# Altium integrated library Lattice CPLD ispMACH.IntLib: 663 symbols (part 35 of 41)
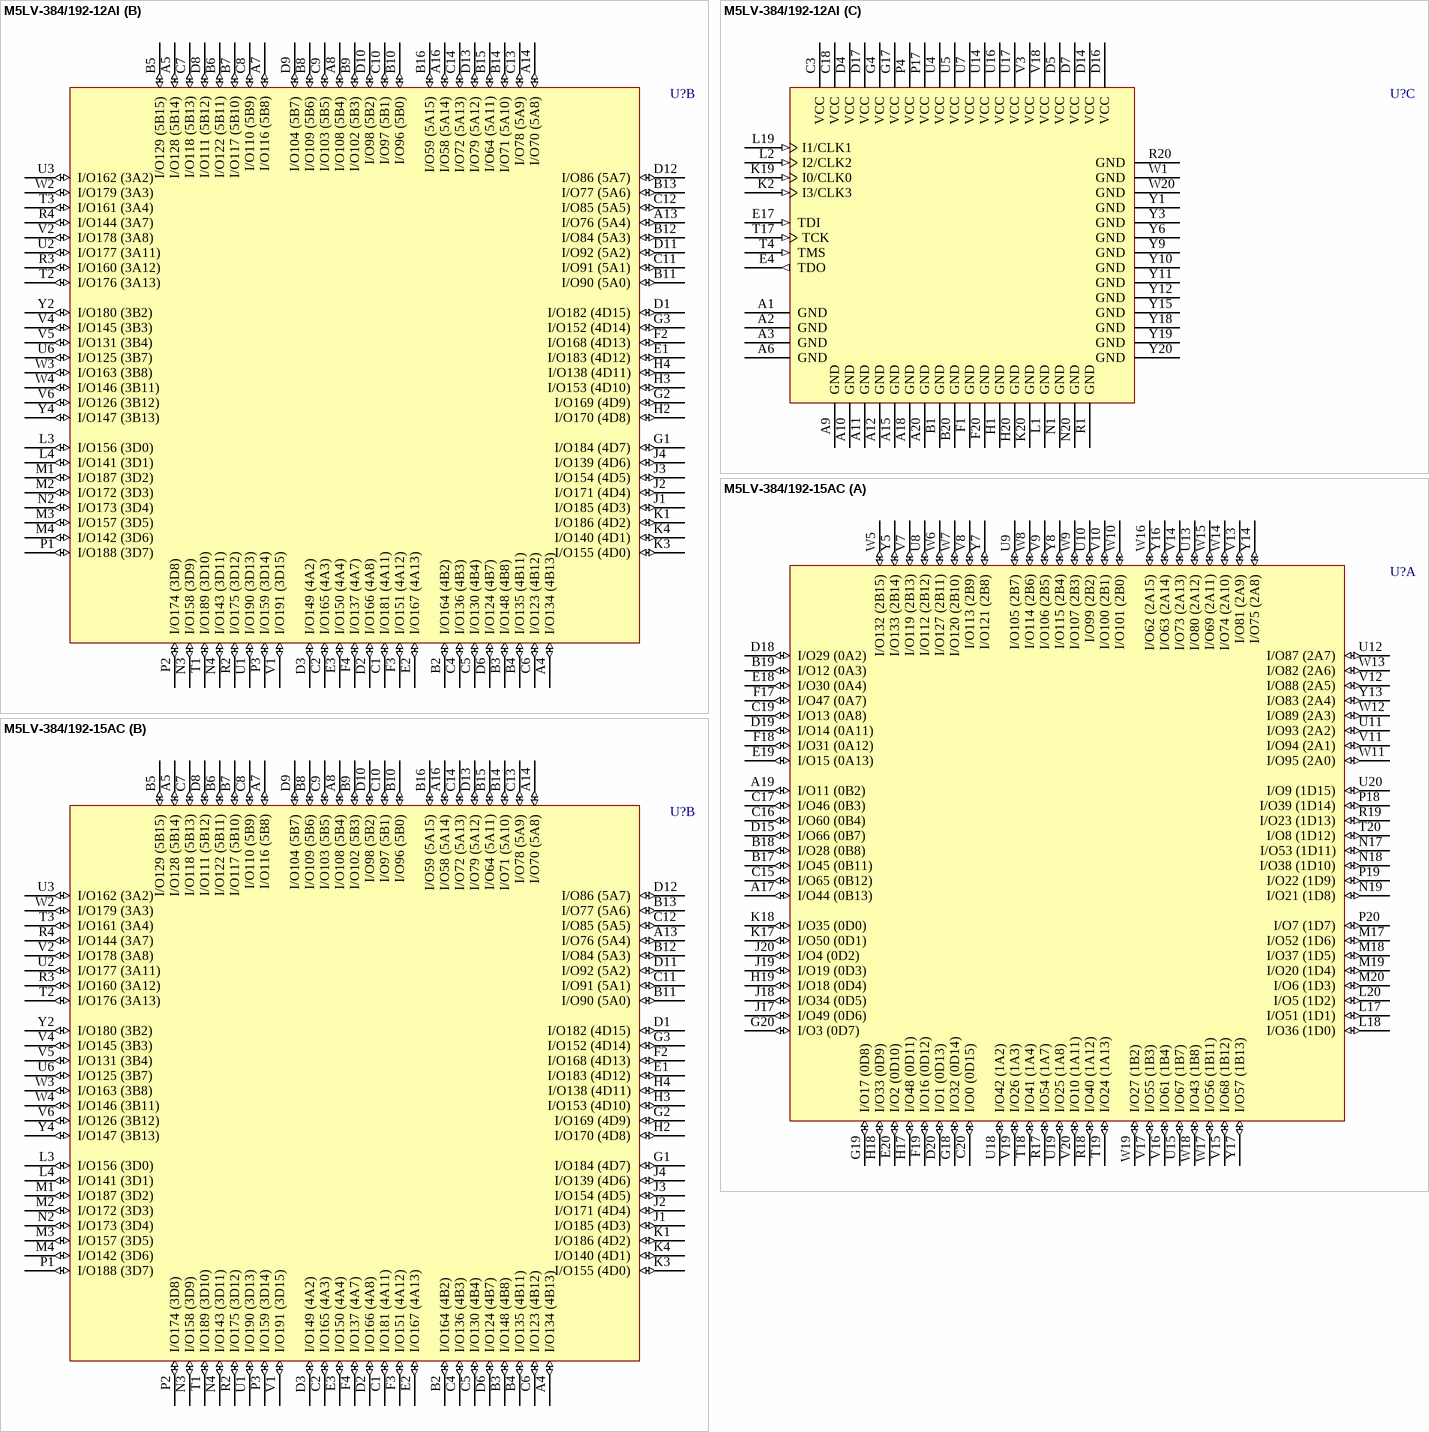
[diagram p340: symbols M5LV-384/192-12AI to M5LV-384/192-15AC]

## M5LV-384/192-12AI
designator U?
High-Density and High-I/O Complex PLD
footprint SBGA256 (BGA, 256-Leads, Body 27x27mm, Pitch 1.27mm)
3D model M5LV-SBGA256 (256-Ball Super Ball Grid Array (SBGA256))
part A pins: A17 I/O44 (0B13) (io), A19 I/O11 (0B2) (io), B17 I/O45 (0B11) (io), B18 I/O28 (0B8) (io), B19 I/O12 (0A3) (io), C15 I/O65 (0B12) (io), C16 I/O60 (0B4) (io), C17 I/O46 (0B3) (io), C19 I/O13 (0A8) (io), C20 I/O0 (0D15) (io), D15 I/O66 (0B7) (io), D18 I/O29 (0A2) (io), D19 I/O14 (0A11) (io), D20 I/O1 (0D13) (io), E18 I/O30 (0A4) (io), E19 I/O15 (0A13) (io), E20 I/O2 (0D10) (io), F17 I/O47 (0A7) (io), F18 I/O31 (0A12) (io), F19 I/O16 (0D12) (io), G18 I/O32 (0D14) (io), G19 I/O17 (0D8) (io), G20 I/O3 (0D7) (io), H17 I/O48 (0D11) (io), H18 I/O33 (0D9) (io), H19 I/O18 (0D4) (io), J17 I/O49 (0D6) (io), J18 I/O34 (0D5) (io), J19 I/O19 (0D3) (io), J20 I/O4 (0D2) (io), K17 I/O50 (0D1) (io), K18 I/O35 (0D0) (io), L17 I/O51 (1D1) (io), L18 I/O36 (1D0) (io), L20 I/O5 (1D2) (io), M17 I/O52 (1D6) (io), M18 I/O37 (1D5) (io), M19 I/O20 (1D4) (io), M20 I/O6 (1D3) (io), N17 I/O53 (1D11) (io), N18 I/O38 (1D10) (io), N19 I/O21 (1D8) (io), P18 I/O39 (1D14) (io), P19 I/O22 (1D9) (io), P20 I/O7 (1D7) (io), R17 I/O54 (1A7) (io), R18 I/O40 (1A12) (io), R19 I/O23 (1D13) (io), T18 I/O41 (1A4) (io), T19 I/O24 (1A13) (io), T20 I/O8 (1D12) (io), U8 I/O112 (2B12) (io), U9 I/O105 (2B7) (io), U10 I/O99 (2B2) (io), U11 I/O93 (2A2) (io), U12 I/O87 (2A7) (io), U13 I/O80 (2A12) (io), U15 I/O67 (1B7) (io), U18 I/O42 (1A2) (io), U19 I/O25 (1A8) (io), U20 I/O9 (1D15) (io), V7 I/O119 (2B13) (io), V8 I/O113 (2B9) (io), V9 I/O106 (2B5) (io), V10 I/O100 (2B1) (io), V11 I/O94 (2A1) (io), V12 I/O88 (2A5) (io), V13 I/O81 (2A9) (io), V14 I/O73 (2A13) (io), V15 I/O68 (1B12) (io), V16 I/O61 (1B4) (io), V17 I/O55 (1B3) (io), V19 I/O26 (1A3) (io), V20 I/O10 (1A11) (io), W5 I/O132 (2B15) (io), W6 I/O127 (2B11) (io), W7 I/O120 (2B10) (io), W8 I/O114 (2B6) (io), W9 I/O107 (2B3) (io), W10 I/O101 (2B0) (io), W11 I/O95 (2A0) (io), W12 I/O89 (2A3) (io), W13 I/O82 (2A6) (io), W14 I/O74 (2A10) (io), W15 I/O69 (2A11) (io), W16 I/O62 (2A15) (io), W17 I/O56 (1B11) (io), W18 I/O43 (1B8) (io), W19 I/O27 (1B2) (io), Y5 I/O133 (2B14) (io), Y7 I/O121 (2B8) (io), Y8 I/O115 (2B4) (io), Y13 I/O83 (2A4) (io), Y14 I/O75 (2A8) (io), Y16 I/O63 (2A14) (io), Y17 I/O57 (1B13) (io)
part B pins: A4 I/O134 (4B13) (io), A5 I/O128 (5B14) (io), A7 I/O116 (5B8) (io), A8 I/O108 (5B4) (io), A13 I/O76 (5A4) (io), A14 I/O70 (5A8) (io), A16 I/O58 (5A14) (io), B2 I/O164 (4B2) (io), B3 I/O148 (4B8) (io), B4 I/O135 (4B11) (io), B5 I/O129 (5B15) (io), B6 I/O122 (5B11) (io), B7 I/O117 (5B10) (io), B8 I/O109 (5B6) (io), B9 I/O102 (5B3) (io), B10 I/O96 (5B0) (io), B11 I/O90 (5A0) (io), B12 I/O84 (5A3) (io), B13 I/O77 (5A6) (io), B14 I/O71 (5A10) (io), B15 I/O64 (5A11) (io), B16 I/O59 (5A15) (io), C1 I/O181 (4A11) (io), C2 I/O165 (4A3) (io), C4 I/O136 (4B3) (io), C5 I/O130 (4B4) (io), C6 I/O123 (4B12) (io), C7 I/O118 (5B13) (io), C8 I/O110 (5B9) (io), C9 I/O103 (5B5) (io), C10 I/O97 (5B1) (io), C11 I/O91 (5A1) (io), C12 I/O85 (5A5) (io), C13 I/O78 (5A9) (io), C14 I/O72 (5A13) (io), D1 I/O182 (4D15) (io), D2 I/O166 (4A8) (io), D3 I/O149 (4A2) (io), D6 I/O124 (4B7) (io), D8 I/O111 (5B12) (io), D9 I/O104 (5B7) (io), D10 I/O98 (5B2) (io), D11 I/O92 (5A2) (io), D12 I/O86 (5A7) (io), D13 I/O79 (5A12) (io), E1 I/O183 (4D12) (io), E2 I/O167 (4A13) (io), E3 I/O150 (4A4) (io), F2 I/O168 (4D13) (io), F3 I/O151 (4A12) (io), F4 I/O137 (4A7) (io), G1 I/O184 (4D7) (io), G2 I/O169 (4D9) (io), G3 I/O152 (4D14) (io), H2 I/O170 (4D8) (io), H3 I/O153 (4D10) (io), H4 I/O138 (4D11) (io), J1 I/O185 (4D3) (io), J2 I/O171 (4D4) (io), J3 I/O154 (4D5) (io), J4 I/O139 (4D6) (io), K1 I/O186 (4D2) (io), K3 I/O155 (4D0) (io), K4 I/O140 (4D1) (io), L3 I/O156 (3D0) (io), L4 I/O141 (3D1) (io), M1 I/O187 (3D2) (io), M2 I/O172 (3D3) (io), M3 I/O157 (3D5) (io), M4 I/O142 (3D6) (io), N2 I/O173 (3D4) (io), N3 I/O158 (3D9) (io), N4 I/O143 (3D11) (io), P1 I/O188 (3D7) (io), P2 I/O174 (3D8) (io), P3 I/O159 (3D14) (io), R2 I/O175 (3D12) (io), R3 I/O160 (3A12) (io), R4 I/O144 (3A7) (io), T1 I/O189 (3D10) (io), T2 I/O176 (3A13) (io), T3 I/O161 (3A4) (io), U1 I/O190 (3D13) (io), U2 I/O177 (3A11) (io), U3 I/O162 (3A2) (io), U6 I/O125 (3B7) (io), V1 I/O191 (3D15) (io), V2 I/O178 (3A8) (io), V4 I/O145 (3B3) (io), V5 I/O131 (3B4) (io), V6 I/O126 (3B12) (io), W2 I/O179 (3A3) (io), W3 I/O163 (3B8) (io), W4 I/O146 (3B11) (io), Y2 I/O180 (3B2) (io), Y4 I/O147 (3B13) (io)
part C pins: A1 GND (power), A2 GND (power), A3 GND (power), A6 GND (power), A9 GND (power), A10 GND (power), A11 GND (power), A12 GND (power), A15 GND (power), A18 GND (power), A20 GND (power), B1 GND (power), B20 GND (power), C3 VCC (power), C18 VCC (power), D4 VCC (power), D5 VCC (power), D7 VCC (power), D14 VCC (power), D16 VCC (power), D17 VCC (power), E4 TDO (out), E17 TDI (in), F1 GND (power), F20 GND (power), G4 VCC (power), G17 VCC (power), H1 GND (power), H20 GND (power), K2 I3/CLK3 (in), K19 I0/CLK0 (in), K20 GND (power), L1 GND (power), L2 I2/CLK2 (in), L19 I1/CLK1 (in), N1 GND (power), N20 GND (power), P4 VCC (power), P17 VCC (power), R1 GND (power), R20 GND (power), T4 TMS (in), T17 TCK (in), U4 VCC (power), U5 VCC (power), U7 VCC (power), U14 VCC (power), U16 VCC (power), U17 VCC (power), V3 VCC (power), V18 VCC (power), W1 GND (power), W20 GND (power), Y1 GND (power), Y3 GND (power), Y6 GND (power), Y9 GND (power), Y10 GND (power), Y11 GND (power), Y12 GND (power), Y15 GND (power), Y18 GND (power), Y19 GND (power), Y20 GND (power)

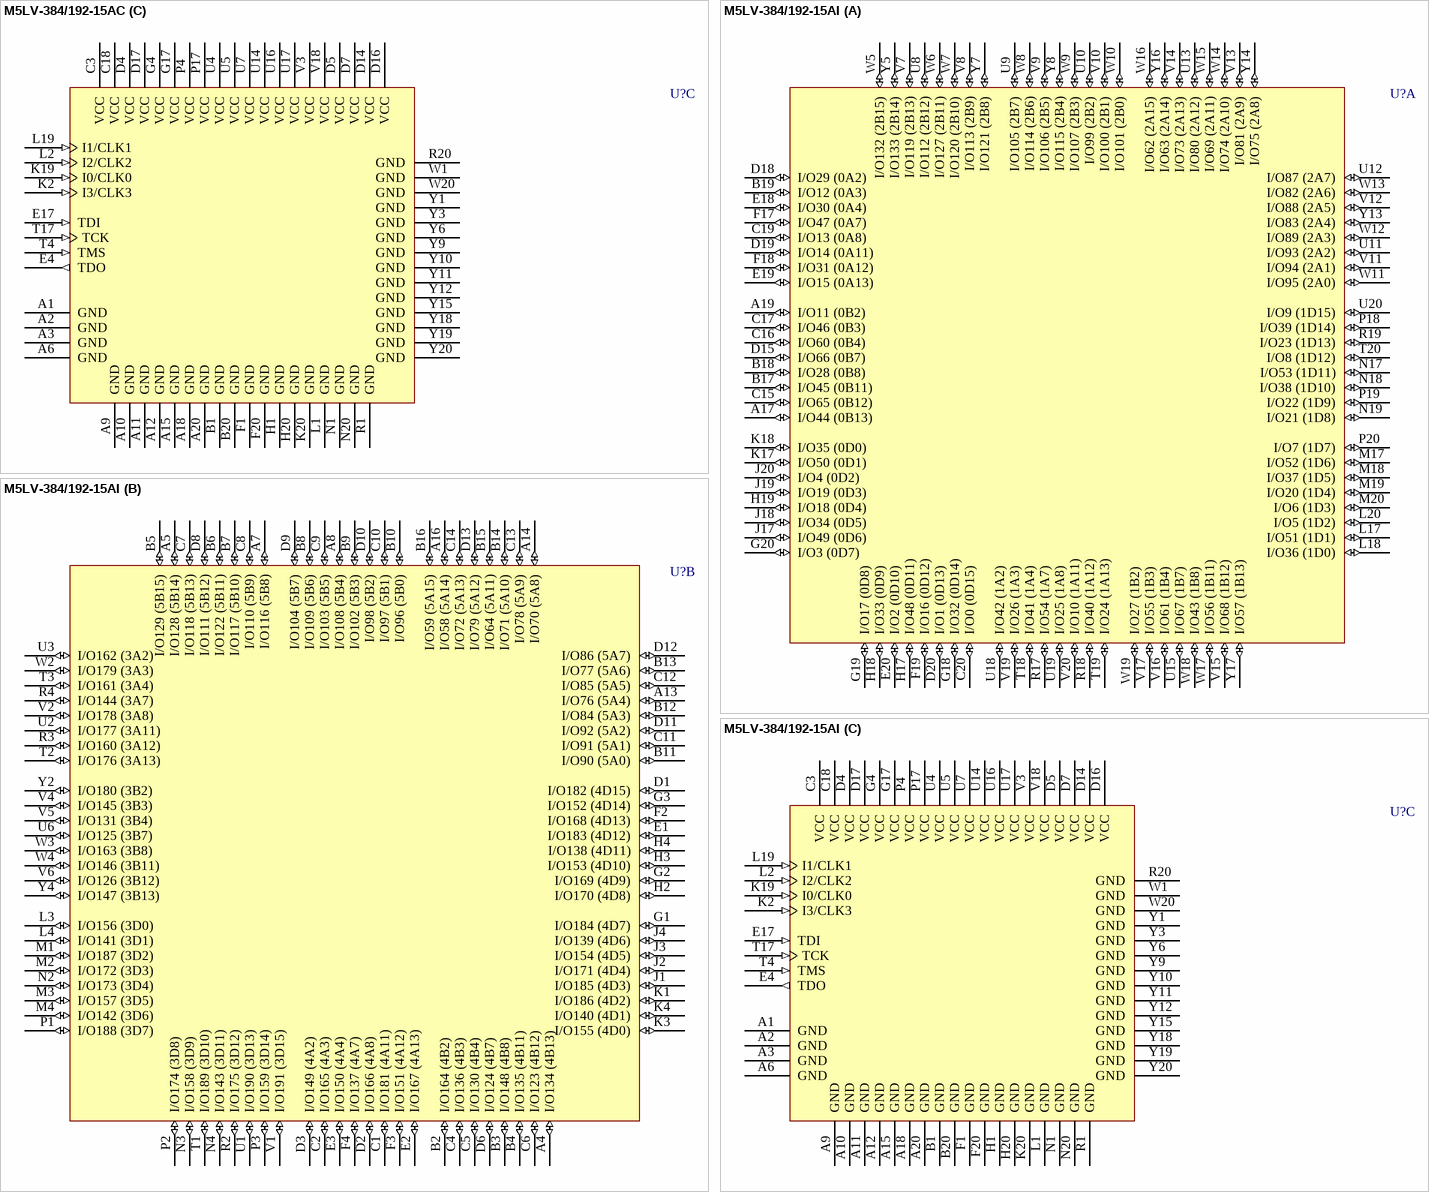
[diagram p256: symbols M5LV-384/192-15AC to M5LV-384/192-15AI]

## M5LV-384/192-15AC
designator U?
High-Density and High-I/O Complex PLD
footprint SBGA256 (BGA, 256-Leads, Body 27x27mm, Pitch 1.27mm)
3D model M5LV-SBGA256 (256-Ball Super Ball Grid Array (SBGA256))
part A pins: A17 I/O44 (0B13) (io), A19 I/O11 (0B2) (io), B17 I/O45 (0B11) (io), B18 I/O28 (0B8) (io), B19 I/O12 (0A3) (io), C15 I/O65 (0B12) (io), C16 I/O60 (0B4) (io), C17 I/O46 (0B3) (io), C19 I/O13 (0A8) (io), C20 I/O0 (0D15) (io), D15 I/O66 (0B7) (io), D18 I/O29 (0A2) (io), D19 I/O14 (0A11) (io), D20 I/O1 (0D13) (io), E18 I/O30 (0A4) (io), E19 I/O15 (0A13) (io), E20 I/O2 (0D10) (io), F17 I/O47 (0A7) (io), F18 I/O31 (0A12) (io), F19 I/O16 (0D12) (io), G18 I/O32 (0D14) (io), G19 I/O17 (0D8) (io), G20 I/O3 (0D7) (io), H17 I/O48 (0D11) (io), H18 I/O33 (0D9) (io), H19 I/O18 (0D4) (io), J17 I/O49 (0D6) (io), J18 I/O34 (0D5) (io), J19 I/O19 (0D3) (io), J20 I/O4 (0D2) (io), K17 I/O50 (0D1) (io), K18 I/O35 (0D0) (io), L17 I/O51 (1D1) (io), L18 I/O36 (1D0) (io), L20 I/O5 (1D2) (io), M17 I/O52 (1D6) (io), M18 I/O37 (1D5) (io), M19 I/O20 (1D4) (io), M20 I/O6 (1D3) (io), N17 I/O53 (1D11) (io), N18 I/O38 (1D10) (io), N19 I/O21 (1D8) (io), P18 I/O39 (1D14) (io), P19 I/O22 (1D9) (io), P20 I/O7 (1D7) (io), R17 I/O54 (1A7) (io), R18 I/O40 (1A12) (io), R19 I/O23 (1D13) (io), T18 I/O41 (1A4) (io), T19 I/O24 (1A13) (io), T20 I/O8 (1D12) (io), U8 I/O112 (2B12) (io), U9 I/O105 (2B7) (io), U10 I/O99 (2B2) (io), U11 I/O93 (2A2) (io), U12 I/O87 (2A7) (io), U13 I/O80 (2A12) (io), U15 I/O67 (1B7) (io), U18 I/O42 (1A2) (io), U19 I/O25 (1A8) (io), U20 I/O9 (1D15) (io), V7 I/O119 (2B13) (io), V8 I/O113 (2B9) (io), V9 I/O106 (2B5) (io), V10 I/O100 (2B1) (io), V11 I/O94 (2A1) (io), V12 I/O88 (2A5) (io), V13 I/O81 (2A9) (io), V14 I/O73 (2A13) (io), V15 I/O68 (1B12) (io), V16 I/O61 (1B4) (io), V17 I/O55 (1B3) (io), V19 I/O26 (1A3) (io), V20 I/O10 (1A11) (io), W5 I/O132 (2B15) (io), W6 I/O127 (2B11) (io), W7 I/O120 (2B10) (io), W8 I/O114 (2B6) (io), W9 I/O107 (2B3) (io), W10 I/O101 (2B0) (io), W11 I/O95 (2A0) (io), W12 I/O89 (2A3) (io), W13 I/O82 (2A6) (io), W14 I/O74 (2A10) (io), W15 I/O69 (2A11) (io), W16 I/O62 (2A15) (io), W17 I/O56 (1B11) (io), W18 I/O43 (1B8) (io), W19 I/O27 (1B2) (io), Y5 I/O133 (2B14) (io), Y7 I/O121 (2B8) (io), Y8 I/O115 (2B4) (io), Y13 I/O83 (2A4) (io), Y14 I/O75 (2A8) (io), Y16 I/O63 (2A14) (io), Y17 I/O57 (1B13) (io)
part B pins: A4 I/O134 (4B13) (io), A5 I/O128 (5B14) (io), A7 I/O116 (5B8) (io), A8 I/O108 (5B4) (io), A13 I/O76 (5A4) (io), A14 I/O70 (5A8) (io), A16 I/O58 (5A14) (io), B2 I/O164 (4B2) (io), B3 I/O148 (4B8) (io), B4 I/O135 (4B11) (io), B5 I/O129 (5B15) (io), B6 I/O122 (5B11) (io), B7 I/O117 (5B10) (io), B8 I/O109 (5B6) (io), B9 I/O102 (5B3) (io), B10 I/O96 (5B0) (io), B11 I/O90 (5A0) (io), B12 I/O84 (5A3) (io), B13 I/O77 (5A6) (io), B14 I/O71 (5A10) (io), B15 I/O64 (5A11) (io), B16 I/O59 (5A15) (io), C1 I/O181 (4A11) (io), C2 I/O165 (4A3) (io), C4 I/O136 (4B3) (io), C5 I/O130 (4B4) (io), C6 I/O123 (4B12) (io), C7 I/O118 (5B13) (io), C8 I/O110 (5B9) (io), C9 I/O103 (5B5) (io), C10 I/O97 (5B1) (io), C11 I/O91 (5A1) (io), C12 I/O85 (5A5) (io), C13 I/O78 (5A9) (io), C14 I/O72 (5A13) (io), D1 I/O182 (4D15) (io), D2 I/O166 (4A8) (io), D3 I/O149 (4A2) (io), D6 I/O124 (4B7) (io), D8 I/O111 (5B12) (io), D9 I/O104 (5B7) (io), D10 I/O98 (5B2) (io), D11 I/O92 (5A2) (io), D12 I/O86 (5A7) (io), D13 I/O79 (5A12) (io), E1 I/O183 (4D12) (io), E2 I/O167 (4A13) (io), E3 I/O150 (4A4) (io), F2 I/O168 (4D13) (io), F3 I/O151 (4A12) (io), F4 I/O137 (4A7) (io), G1 I/O184 (4D7) (io), G2 I/O169 (4D9) (io), G3 I/O152 (4D14) (io), H2 I/O170 (4D8) (io), H3 I/O153 (4D10) (io), H4 I/O138 (4D11) (io), J1 I/O185 (4D3) (io), J2 I/O171 (4D4) (io), J3 I/O154 (4D5) (io), J4 I/O139 (4D6) (io), K1 I/O186 (4D2) (io), K3 I/O155 (4D0) (io), K4 I/O140 (4D1) (io), L3 I/O156 (3D0) (io), L4 I/O141 (3D1) (io), M1 I/O187 (3D2) (io), M2 I/O172 (3D3) (io), M3 I/O157 (3D5) (io), M4 I/O142 (3D6) (io), N2 I/O173 (3D4) (io), N3 I/O158 (3D9) (io), N4 I/O143 (3D11) (io), P1 I/O188 (3D7) (io), P2 I/O174 (3D8) (io), P3 I/O159 (3D14) (io), R2 I/O175 (3D12) (io), R3 I/O160 (3A12) (io), R4 I/O144 (3A7) (io), T1 I/O189 (3D10) (io), T2 I/O176 (3A13) (io), T3 I/O161 (3A4) (io), U1 I/O190 (3D13) (io), U2 I/O177 (3A11) (io), U3 I/O162 (3A2) (io), U6 I/O125 (3B7) (io), V1 I/O191 (3D15) (io), V2 I/O178 (3A8) (io), V4 I/O145 (3B3) (io), V5 I/O131 (3B4) (io), V6 I/O126 (3B12) (io), W2 I/O179 (3A3) (io), W3 I/O163 (3B8) (io), W4 I/O146 (3B11) (io), Y2 I/O180 (3B2) (io), Y4 I/O147 (3B13) (io)
part C pins: A1 GND (power), A2 GND (power), A3 GND (power), A6 GND (power), A9 GND (power), A10 GND (power), A11 GND (power), A12 GND (power), A15 GND (power), A18 GND (power), A20 GND (power), B1 GND (power), B20 GND (power), C3 VCC (power), C18 VCC (power), D4 VCC (power), D5 VCC (power), D7 VCC (power), D14 VCC (power), D16 VCC (power), D17 VCC (power), E4 TDO (out), E17 TDI (in), F1 GND (power), F20 GND (power), G4 VCC (power), G17 VCC (power), H1 GND (power), H20 GND (power), K2 I3/CLK3 (in), K19 I0/CLK0 (in), K20 GND (power), L1 GND (power), L2 I2/CLK2 (in), L19 I1/CLK1 (in), N1 GND (power), N20 GND (power), P4 VCC (power), P17 VCC (power), R1 GND (power), R20 GND (power), T4 TMS (in), T17 TCK (in), U4 VCC (power), U5 VCC (power), U7 VCC (power), U14 VCC (power), U16 VCC (power), U17 VCC (power), V3 VCC (power), V18 VCC (power), W1 GND (power), W20 GND (power), Y1 GND (power), Y3 GND (power), Y6 GND (power), Y9 GND (power), Y10 GND (power), Y11 GND (power), Y12 GND (power), Y15 GND (power), Y18 GND (power), Y19 GND (power), Y20 GND (power)

## M5LV-384/192-15AI
designator U?
High-Density and High-I/O Complex PLD
footprint SBGA256 (BGA, 256-Leads, Body 27x27mm, Pitch 1.27mm)
3D model M5LV-SBGA256 (256-Ball Super Ball Grid Array (SBGA256))
part A pins: A17 I/O44 (0B13) (io), A19 I/O11 (0B2) (io), B17 I/O45 (0B11) (io), B18 I/O28 (0B8) (io), B19 I/O12 (0A3) (io), C15 I/O65 (0B12) (io), C16 I/O60 (0B4) (io), C17 I/O46 (0B3) (io), C19 I/O13 (0A8) (io), C20 I/O0 (0D15) (io), D15 I/O66 (0B7) (io), D18 I/O29 (0A2) (io), D19 I/O14 (0A11) (io), D20 I/O1 (0D13) (io), E18 I/O30 (0A4) (io), E19 I/O15 (0A13) (io), E20 I/O2 (0D10) (io), F17 I/O47 (0A7) (io), F18 I/O31 (0A12) (io), F19 I/O16 (0D12) (io), G18 I/O32 (0D14) (io), G19 I/O17 (0D8) (io), G20 I/O3 (0D7) (io), H17 I/O48 (0D11) (io), H18 I/O33 (0D9) (io), H19 I/O18 (0D4) (io), J17 I/O49 (0D6) (io), J18 I/O34 (0D5) (io), J19 I/O19 (0D3) (io), J20 I/O4 (0D2) (io), K17 I/O50 (0D1) (io), K18 I/O35 (0D0) (io), L17 I/O51 (1D1) (io), L18 I/O36 (1D0) (io), L20 I/O5 (1D2) (io), M17 I/O52 (1D6) (io), M18 I/O37 (1D5) (io), M19 I/O20 (1D4) (io), M20 I/O6 (1D3) (io), N17 I/O53 (1D11) (io), N18 I/O38 (1D10) (io), N19 I/O21 (1D8) (io), P18 I/O39 (1D14) (io), P19 I/O22 (1D9) (io), P20 I/O7 (1D7) (io), R17 I/O54 (1A7) (io), R18 I/O40 (1A12) (io), R19 I/O23 (1D13) (io), T18 I/O41 (1A4) (io), T19 I/O24 (1A13) (io), T20 I/O8 (1D12) (io), U8 I/O112 (2B12) (io), U9 I/O105 (2B7) (io), U10 I/O99 (2B2) (io), U11 I/O93 (2A2) (io), U12 I/O87 (2A7) (io), U13 I/O80 (2A12) (io), U15 I/O67 (1B7) (io), U18 I/O42 (1A2) (io), U19 I/O25 (1A8) (io), U20 I/O9 (1D15) (io), V7 I/O119 (2B13) (io), V8 I/O113 (2B9) (io), V9 I/O106 (2B5) (io), V10 I/O100 (2B1) (io), V11 I/O94 (2A1) (io), V12 I/O88 (2A5) (io), V13 I/O81 (2A9) (io), V14 I/O73 (2A13) (io), V15 I/O68 (1B12) (io), V16 I/O61 (1B4) (io), V17 I/O55 (1B3) (io), V19 I/O26 (1A3) (io), V20 I/O10 (1A11) (io), W5 I/O132 (2B15) (io), W6 I/O127 (2B11) (io), W7 I/O120 (2B10) (io), W8 I/O114 (2B6) (io), W9 I/O107 (2B3) (io), W10 I/O101 (2B0) (io), W11 I/O95 (2A0) (io), W12 I/O89 (2A3) (io), W13 I/O82 (2A6) (io), W14 I/O74 (2A10) (io), W15 I/O69 (2A11) (io), W16 I/O62 (2A15) (io), W17 I/O56 (1B11) (io), W18 I/O43 (1B8) (io), W19 I/O27 (1B2) (io), Y5 I/O133 (2B14) (io), Y7 I/O121 (2B8) (io), Y8 I/O115 (2B4) (io), Y13 I/O83 (2A4) (io), Y14 I/O75 (2A8) (io), Y16 I/O63 (2A14) (io), Y17 I/O57 (1B13) (io)
part B pins: A4 I/O134 (4B13) (io), A5 I/O128 (5B14) (io), A7 I/O116 (5B8) (io), A8 I/O108 (5B4) (io), A13 I/O76 (5A4) (io), A14 I/O70 (5A8) (io), A16 I/O58 (5A14) (io), B2 I/O164 (4B2) (io), B3 I/O148 (4B8) (io), B4 I/O135 (4B11) (io), B5 I/O129 (5B15) (io), B6 I/O122 (5B11) (io), B7 I/O117 (5B10) (io), B8 I/O109 (5B6) (io), B9 I/O102 (5B3) (io), B10 I/O96 (5B0) (io), B11 I/O90 (5A0) (io), B12 I/O84 (5A3) (io), B13 I/O77 (5A6) (io), B14 I/O71 (5A10) (io), B15 I/O64 (5A11) (io), B16 I/O59 (5A15) (io), C1 I/O181 (4A11) (io), C2 I/O165 (4A3) (io), C4 I/O136 (4B3) (io), C5 I/O130 (4B4) (io), C6 I/O123 (4B12) (io), C7 I/O118 (5B13) (io), C8 I/O110 (5B9) (io), C9 I/O103 (5B5) (io), C10 I/O97 (5B1) (io), C11 I/O91 (5A1) (io), C12 I/O85 (5A5) (io), C13 I/O78 (5A9) (io), C14 I/O72 (5A13) (io), D1 I/O182 (4D15) (io), D2 I/O166 (4A8) (io), D3 I/O149 (4A2) (io), D6 I/O124 (4B7) (io), D8 I/O111 (5B12) (io), D9 I/O104 (5B7) (io), D10 I/O98 (5B2) (io), D11 I/O92 (5A2) (io), D12 I/O86 (5A7) (io), D13 I/O79 (5A12) (io), E1 I/O183 (4D12) (io), E2 I/O167 (4A13) (io), E3 I/O150 (4A4) (io), F2 I/O168 (4D13) (io), F3 I/O151 (4A12) (io), F4 I/O137 (4A7) (io), G1 I/O184 (4D7) (io), G2 I/O169 (4D9) (io), G3 I/O152 (4D14) (io), H2 I/O170 (4D8) (io), H3 I/O153 (4D10) (io), H4 I/O138 (4D11) (io), J1 I/O185 (4D3) (io), J2 I/O171 (4D4) (io), J3 I/O154 (4D5) (io), J4 I/O139 (4D6) (io), K1 I/O186 (4D2) (io), K3 I/O155 (4D0) (io), K4 I/O140 (4D1) (io), L3 I/O156 (3D0) (io), L4 I/O141 (3D1) (io), M1 I/O187 (3D2) (io), M2 I/O172 (3D3) (io), M3 I/O157 (3D5) (io), M4 I/O142 (3D6) (io), N2 I/O173 (3D4) (io), N3 I/O158 (3D9) (io), N4 I/O143 (3D11) (io), P1 I/O188 (3D7) (io), P2 I/O174 (3D8) (io), P3 I/O159 (3D14) (io), R2 I/O175 (3D12) (io), R3 I/O160 (3A12) (io), R4 I/O144 (3A7) (io), T1 I/O189 (3D10) (io), T2 I/O176 (3A13) (io), T3 I/O161 (3A4) (io), U1 I/O190 (3D13) (io), U2 I/O177 (3A11) (io), U3 I/O162 (3A2) (io), U6 I/O125 (3B7) (io), V1 I/O191 (3D15) (io), V2 I/O178 (3A8) (io), V4 I/O145 (3B3) (io), V5 I/O131 (3B4) (io), V6 I/O126 (3B12) (io), W2 I/O179 (3A3) (io), W3 I/O163 (3B8) (io), W4 I/O146 (3B11) (io), Y2 I/O180 (3B2) (io), Y4 I/O147 (3B13) (io)
part C pins: A1 GND (power), A2 GND (power), A3 GND (power), A6 GND (power), A9 GND (power), A10 GND (power), A11 GND (power), A12 GND (power), A15 GND (power), A18 GND (power), A20 GND (power), B1 GND (power), B20 GND (power), C3 VCC (power), C18 VCC (power), D4 VCC (power), D5 VCC (power), D7 VCC (power), D14 VCC (power), D16 VCC (power), D17 VCC (power), E4 TDO (out), E17 TDI (in), F1 GND (power), F20 GND (power), G4 VCC (power), G17 VCC (power), H1 GND (power), H20 GND (power), K2 I3/CLK3 (in), K19 I0/CLK0 (in), K20 GND (power), L1 GND (power), L2 I2/CLK2 (in), L19 I1/CLK1 (in), N1 GND (power), N20 GND (power), P4 VCC (power), P17 VCC (power), R1 GND (power), R20 GND (power), T4 TMS (in), T17 TCK (in), U4 VCC (power), U5 VCC (power), U7 VCC (power), U14 VCC (power), U16 VCC (power), U17 VCC (power), V3 VCC (power), V18 VCC (power), W1 GND (power), W20 GND (power), Y1 GND (power), Y3 GND (power), Y6 GND (power), Y9 GND (power), Y10 GND (power), Y11 GND (power), Y12 GND (power), Y15 GND (power), Y18 GND (power), Y19 GND (power), Y20 GND (power)

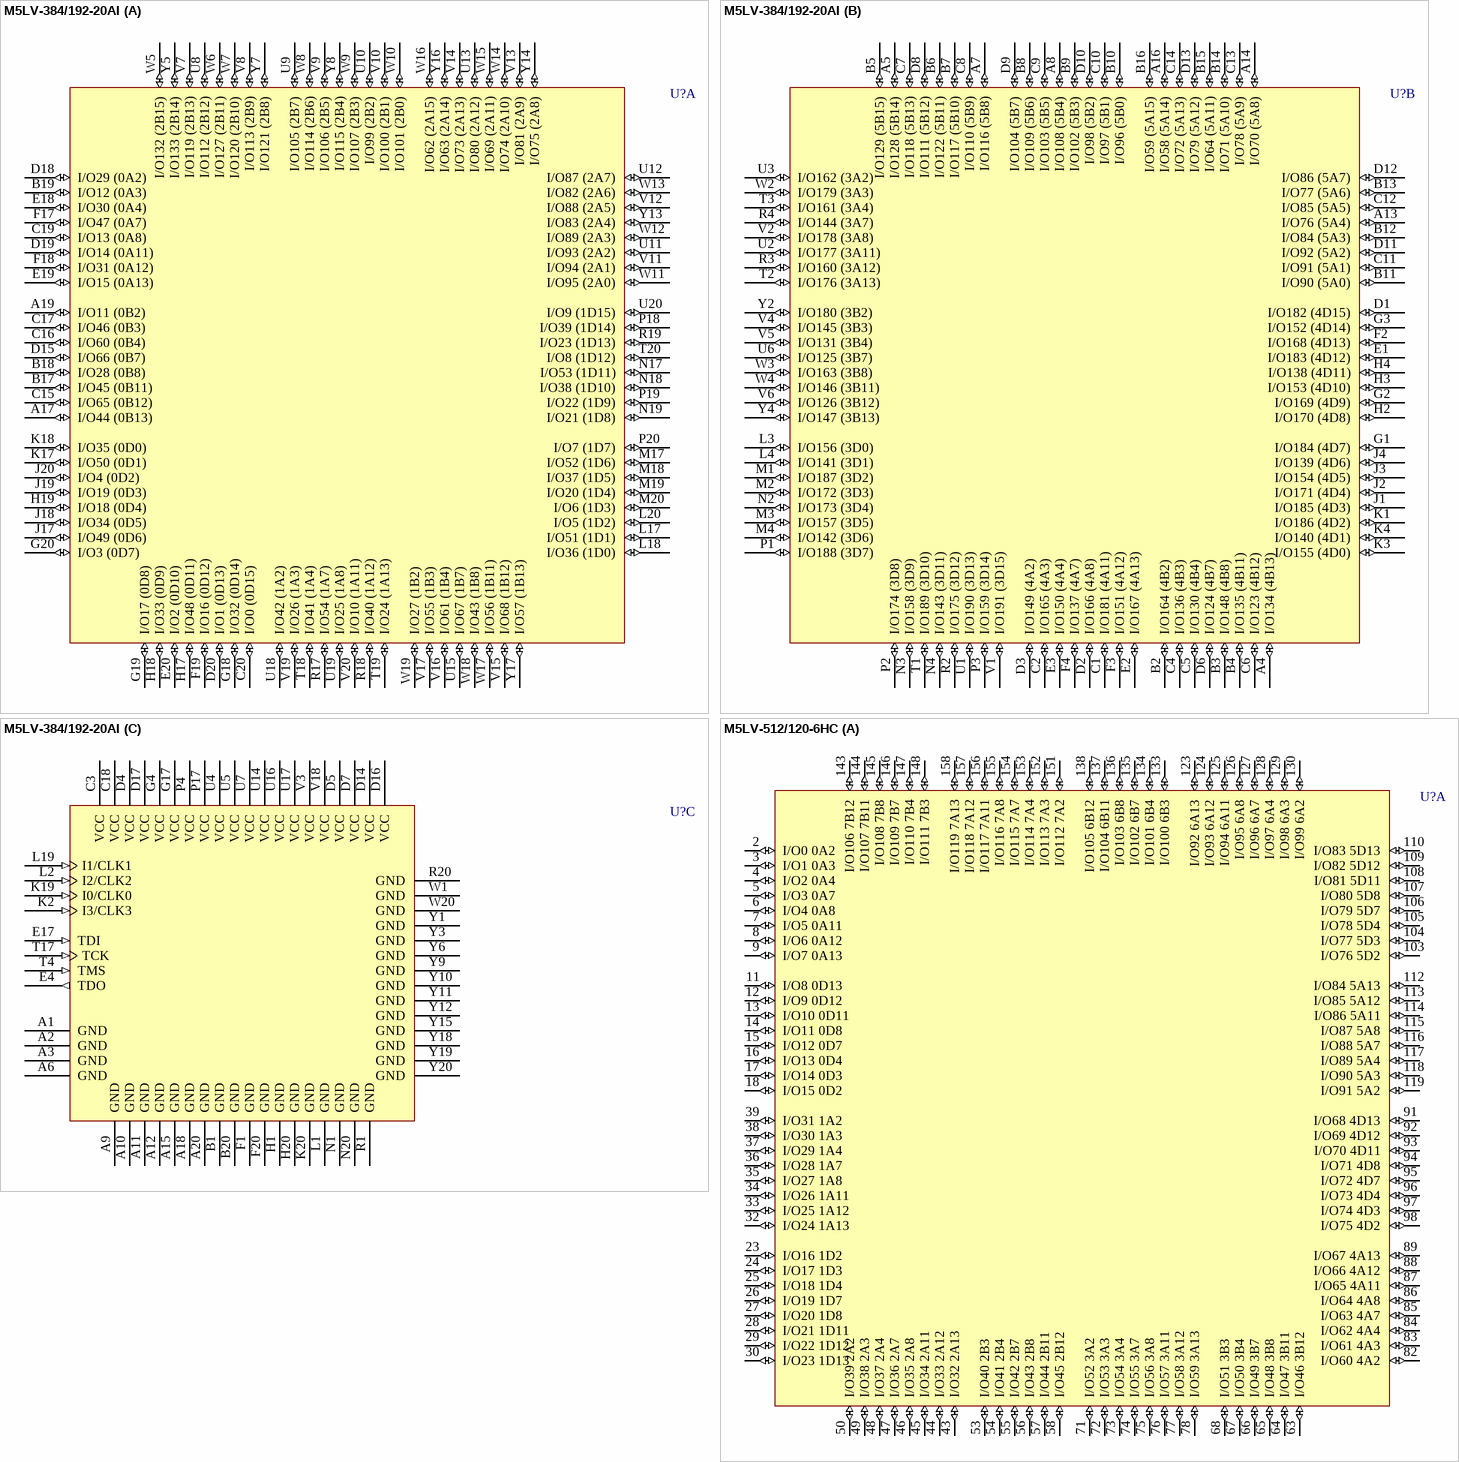
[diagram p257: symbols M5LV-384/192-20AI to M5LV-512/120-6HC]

## M5LV-384/192-20AI
designator U?
High-Density and High-I/O Complex PLD
footprint SBGA256 (BGA, 256-Leads, Body 27x27mm, Pitch 1.27mm)
3D model M5LV-SBGA256 (256-Ball Super Ball Grid Array (SBGA256))
part A pins: A17 I/O44 (0B13) (io), A19 I/O11 (0B2) (io), B17 I/O45 (0B11) (io), B18 I/O28 (0B8) (io), B19 I/O12 (0A3) (io), C15 I/O65 (0B12) (io), C16 I/O60 (0B4) (io), C17 I/O46 (0B3) (io), C19 I/O13 (0A8) (io), C20 I/O0 (0D15) (io), D15 I/O66 (0B7) (io), D18 I/O29 (0A2) (io), D19 I/O14 (0A11) (io), D20 I/O1 (0D13) (io), E18 I/O30 (0A4) (io), E19 I/O15 (0A13) (io), E20 I/O2 (0D10) (io), F17 I/O47 (0A7) (io), F18 I/O31 (0A12) (io), F19 I/O16 (0D12) (io), G18 I/O32 (0D14) (io), G19 I/O17 (0D8) (io), G20 I/O3 (0D7) (io), H17 I/O48 (0D11) (io), H18 I/O33 (0D9) (io), H19 I/O18 (0D4) (io), J17 I/O49 (0D6) (io), J18 I/O34 (0D5) (io), J19 I/O19 (0D3) (io), J20 I/O4 (0D2) (io), K17 I/O50 (0D1) (io), K18 I/O35 (0D0) (io), L17 I/O51 (1D1) (io), L18 I/O36 (1D0) (io), L20 I/O5 (1D2) (io), M17 I/O52 (1D6) (io), M18 I/O37 (1D5) (io), M19 I/O20 (1D4) (io), M20 I/O6 (1D3) (io), N17 I/O53 (1D11) (io), N18 I/O38 (1D10) (io), N19 I/O21 (1D8) (io), P18 I/O39 (1D14) (io), P19 I/O22 (1D9) (io), P20 I/O7 (1D7) (io), R17 I/O54 (1A7) (io), R18 I/O40 (1A12) (io), R19 I/O23 (1D13) (io), T18 I/O41 (1A4) (io), T19 I/O24 (1A13) (io), T20 I/O8 (1D12) (io), U8 I/O112 (2B12) (io), U9 I/O105 (2B7) (io), U10 I/O99 (2B2) (io), U11 I/O93 (2A2) (io), U12 I/O87 (2A7) (io), U13 I/O80 (2A12) (io), U15 I/O67 (1B7) (io), U18 I/O42 (1A2) (io), U19 I/O25 (1A8) (io), U20 I/O9 (1D15) (io), V7 I/O119 (2B13) (io), V8 I/O113 (2B9) (io), V9 I/O106 (2B5) (io), V10 I/O100 (2B1) (io), V11 I/O94 (2A1) (io), V12 I/O88 (2A5) (io), V13 I/O81 (2A9) (io), V14 I/O73 (2A13) (io), V15 I/O68 (1B12) (io), V16 I/O61 (1B4) (io), V17 I/O55 (1B3) (io), V19 I/O26 (1A3) (io), V20 I/O10 (1A11) (io), W5 I/O132 (2B15) (io), W6 I/O127 (2B11) (io), W7 I/O120 (2B10) (io), W8 I/O114 (2B6) (io), W9 I/O107 (2B3) (io), W10 I/O101 (2B0) (io), W11 I/O95 (2A0) (io), W12 I/O89 (2A3) (io), W13 I/O82 (2A6) (io), W14 I/O74 (2A10) (io), W15 I/O69 (2A11) (io), W16 I/O62 (2A15) (io), W17 I/O56 (1B11) (io), W18 I/O43 (1B8) (io), W19 I/O27 (1B2) (io), Y5 I/O133 (2B14) (io), Y7 I/O121 (2B8) (io), Y8 I/O115 (2B4) (io), Y13 I/O83 (2A4) (io), Y14 I/O75 (2A8) (io), Y16 I/O63 (2A14) (io), Y17 I/O57 (1B13) (io)
part B pins: A4 I/O134 (4B13) (io), A5 I/O128 (5B14) (io), A7 I/O116 (5B8) (io), A8 I/O108 (5B4) (io), A13 I/O76 (5A4) (io), A14 I/O70 (5A8) (io), A16 I/O58 (5A14) (io), B2 I/O164 (4B2) (io), B3 I/O148 (4B8) (io), B4 I/O135 (4B11) (io), B5 I/O129 (5B15) (io), B6 I/O122 (5B11) (io), B7 I/O117 (5B10) (io), B8 I/O109 (5B6) (io), B9 I/O102 (5B3) (io), B10 I/O96 (5B0) (io), B11 I/O90 (5A0) (io), B12 I/O84 (5A3) (io), B13 I/O77 (5A6) (io), B14 I/O71 (5A10) (io), B15 I/O64 (5A11) (io), B16 I/O59 (5A15) (io), C1 I/O181 (4A11) (io), C2 I/O165 (4A3) (io), C4 I/O136 (4B3) (io), C5 I/O130 (4B4) (io), C6 I/O123 (4B12) (io), C7 I/O118 (5B13) (io), C8 I/O110 (5B9) (io), C9 I/O103 (5B5) (io), C10 I/O97 (5B1) (io), C11 I/O91 (5A1) (io), C12 I/O85 (5A5) (io), C13 I/O78 (5A9) (io), C14 I/O72 (5A13) (io), D1 I/O182 (4D15) (io), D2 I/O166 (4A8) (io), D3 I/O149 (4A2) (io), D6 I/O124 (4B7) (io), D8 I/O111 (5B12) (io), D9 I/O104 (5B7) (io), D10 I/O98 (5B2) (io), D11 I/O92 (5A2) (io), D12 I/O86 (5A7) (io), D13 I/O79 (5A12) (io), E1 I/O183 (4D12) (io), E2 I/O167 (4A13) (io), E3 I/O150 (4A4) (io), F2 I/O168 (4D13) (io), F3 I/O151 (4A12) (io), F4 I/O137 (4A7) (io), G1 I/O184 (4D7) (io), G2 I/O169 (4D9) (io), G3 I/O152 (4D14) (io), H2 I/O170 (4D8) (io), H3 I/O153 (4D10) (io), H4 I/O138 (4D11) (io), J1 I/O185 (4D3) (io), J2 I/O171 (4D4) (io), J3 I/O154 (4D5) (io), J4 I/O139 (4D6) (io), K1 I/O186 (4D2) (io), K3 I/O155 (4D0) (io), K4 I/O140 (4D1) (io), L3 I/O156 (3D0) (io), L4 I/O141 (3D1) (io), M1 I/O187 (3D2) (io), M2 I/O172 (3D3) (io), M3 I/O157 (3D5) (io), M4 I/O142 (3D6) (io), N2 I/O173 (3D4) (io), N3 I/O158 (3D9) (io), N4 I/O143 (3D11) (io), P1 I/O188 (3D7) (io), P2 I/O174 (3D8) (io), P3 I/O159 (3D14) (io), R2 I/O175 (3D12) (io), R3 I/O160 (3A12) (io), R4 I/O144 (3A7) (io), T1 I/O189 (3D10) (io), T2 I/O176 (3A13) (io), T3 I/O161 (3A4) (io), U1 I/O190 (3D13) (io), U2 I/O177 (3A11) (io), U3 I/O162 (3A2) (io), U6 I/O125 (3B7) (io), V1 I/O191 (3D15) (io), V2 I/O178 (3A8) (io), V4 I/O145 (3B3) (io), V5 I/O131 (3B4) (io), V6 I/O126 (3B12) (io), W2 I/O179 (3A3) (io), W3 I/O163 (3B8) (io), W4 I/O146 (3B11) (io), Y2 I/O180 (3B2) (io), Y4 I/O147 (3B13) (io)
part C pins: A1 GND (power), A2 GND (power), A3 GND (power), A6 GND (power), A9 GND (power), A10 GND (power), A11 GND (power), A12 GND (power), A15 GND (power), A18 GND (power), A20 GND (power), B1 GND (power), B20 GND (power), C3 VCC (power), C18 VCC (power), D4 VCC (power), D5 VCC (power), D7 VCC (power), D14 VCC (power), D16 VCC (power), D17 VCC (power), E4 TDO (out), E17 TDI (in), F1 GND (power), F20 GND (power), G4 VCC (power), G17 VCC (power), H1 GND (power), H20 GND (power), K2 I3/CLK3 (in), K19 I0/CLK0 (in), K20 GND (power), L1 GND (power), L2 I2/CLK2 (in), L19 I1/CLK1 (in), N1 GND (power), N20 GND (power), P4 VCC (power), P17 VCC (power), R1 GND (power), R20 GND (power), T4 TMS (in), T17 TCK (in), U4 VCC (power), U5 VCC (power), U7 VCC (power), U14 VCC (power), U16 VCC (power), U17 VCC (power), V3 VCC (power), V18 VCC (power), W1 GND (power), W20 GND (power), Y1 GND (power), Y3 GND (power), Y6 GND (power), Y9 GND (power), Y10 GND (power), Y11 GND (power), Y12 GND (power), Y15 GND (power), Y18 GND (power), Y19 GND (power), Y20 GND (power)

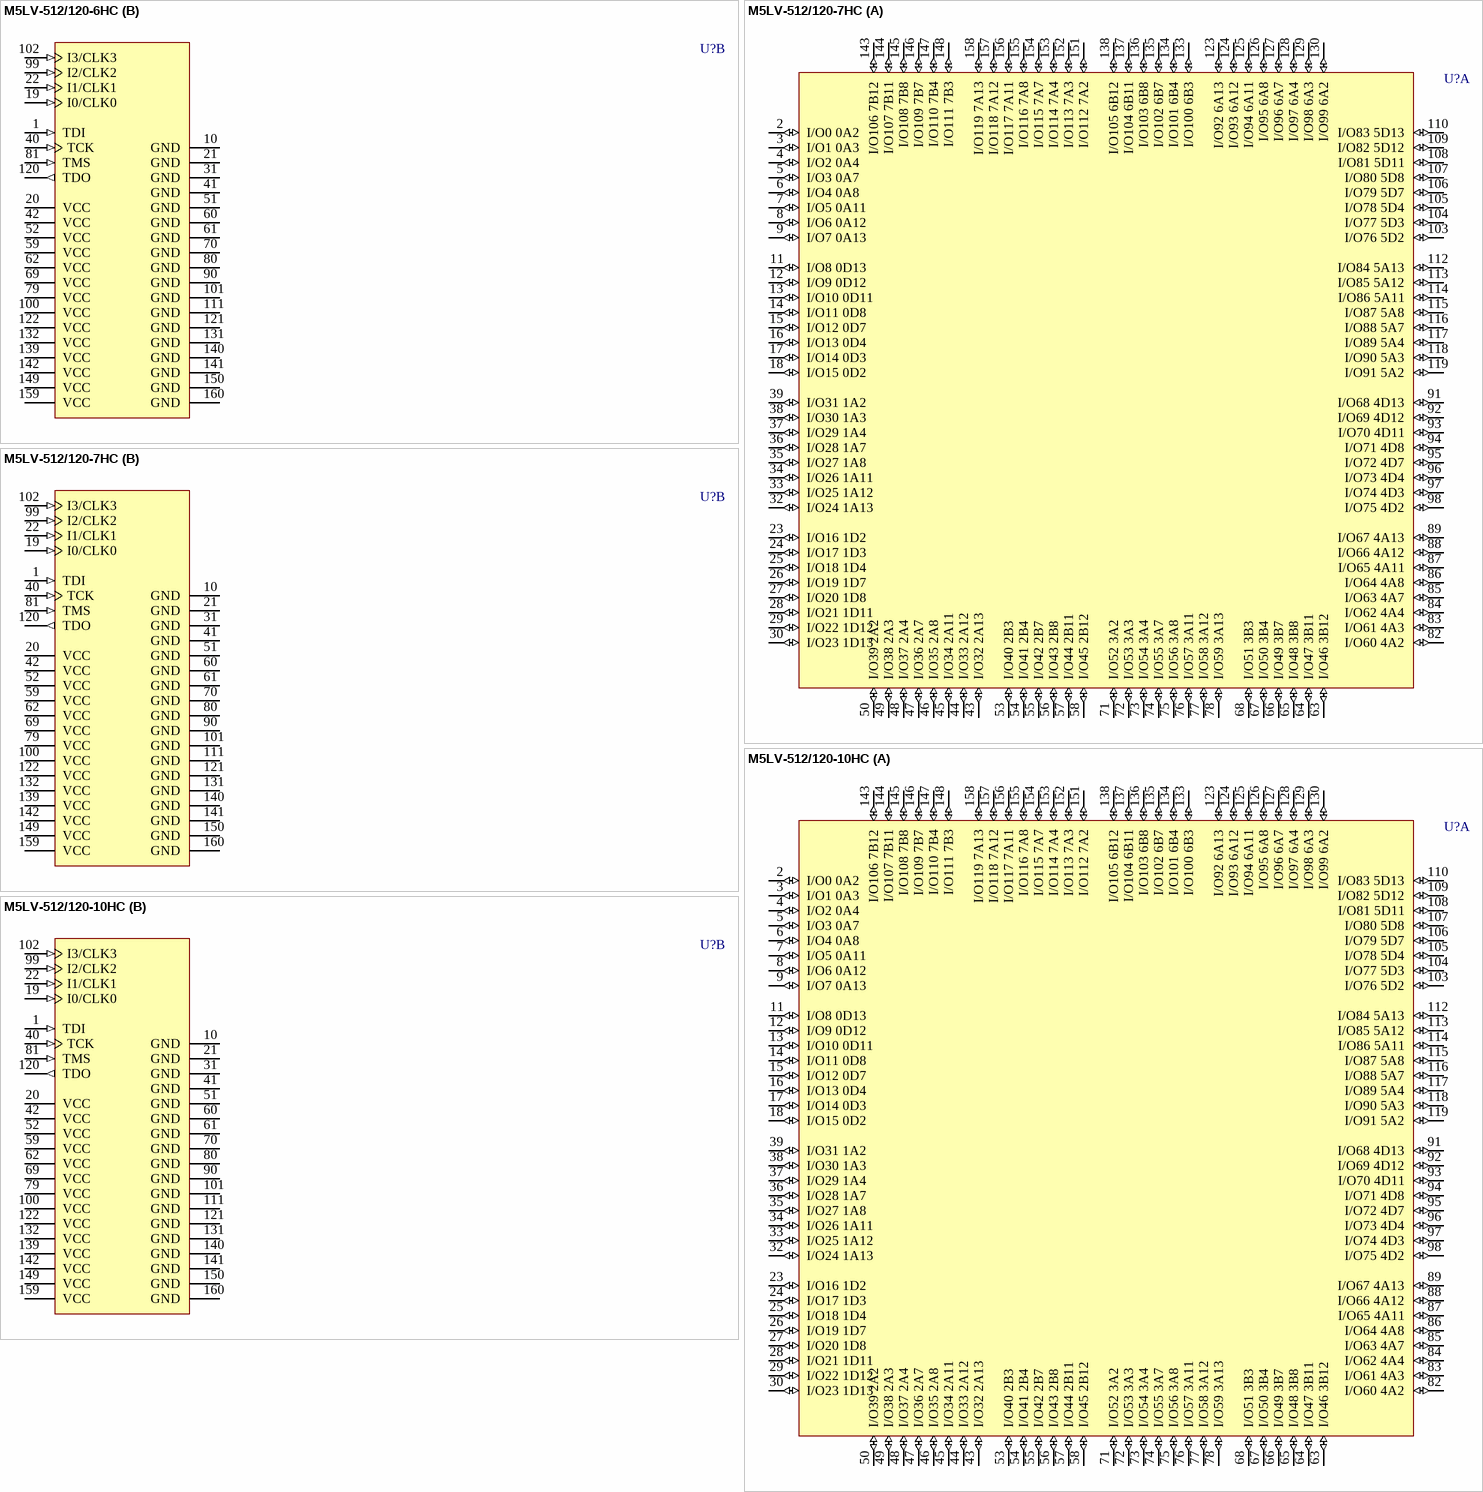
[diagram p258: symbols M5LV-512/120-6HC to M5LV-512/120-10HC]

## M5LV-512/120-6HC
designator U?
High-Density and High-I/O Complex PLD
footprint MQFP160_N (QFP, 160-Leads, Body 27.7 x 27.7mm, Pitch 0.65mm, IPC Medium Density)
footprint MQFP160_L (QFP, 160-Leads, Body 27.7 x 27.7mm, Pitch 0.65mm, IPC High Density)
footprint MQFP160_M (QFP, 160-Leads, Body 27.7 x 27.7mm, Pitch 0.65mm, IPC Low Density)
3D model M5LV-MQFP160 (160-Pin Quad Flat Pack 0.65 mm Pitch)
part A pins: 2 I/O0 0A2 (io), 3 I/O1 0A3 (io), 4 I/O2 0A4 (io), 5 I/O3 0A7 (io), 6 I/O4 0A8 (io), 7 I/O5 0A11 (io), 8 I/O6 0A12 (io), 9 I/O7 0A13 (io), 11 I/O8 0D13 (io), 12 I/O9 0D12 (io), 13 I/O10 0D11 (io), 14 I/O11 0D8 (io), 15 I/O12 0D7 (io), 16 I/O13 0D4 (io), 17 I/O14 0D3 (io), 18 I/O15 0D2 (io), 23 I/O16 1D2 (io), 24 I/O17 1D3 (io), 25 I/O18 1D4 (io), 26 I/O19 1D7 (io), 27 I/O20 1D8 (io), 28 I/O21 1D11 (io), 29 I/O22 1D12 (io), 30 I/O23 1D13 (io), 32 I/O24 1A13 (io), 33 I/O25 1A12 (io), 34 I/O26 1A11 (io), 35 I/O27 1A8 (io), 36 I/O28 1A7 (io), 37 I/O29 1A4 (io), 38 I/O30 1A3 (io), 39 I/O31 1A2 (io), 43 I/O32 2A13 (io), 44 I/O33 2A12 (io), 45 I/O34 2A11 (io), 46 I/O35 2A8 (io), 47 I/O36 2A7 (io), 48 I/O37 2A4 (io), 49 I/O38 2A3 (io), 50 I/O39 2A2 (io), 53 I/O40 2B3 (io), 54 I/O41 2B4 (io), 55 I/O42 2B7 (io), 56 I/O43 2B8 (io), 57 I/O44 2B11 (io), 58 I/O45 2B12 (io), 63 I/O46 3B12 (io), 64 I/O47 3B11 (io), 65 I/O48 3B8 (io), 66 I/O49 3B7 (io), 67 I/O50 3B4 (io), 68 I/O51 3B3 (io), 71 I/O52 3A2 (io), 72 I/O53 3A3 (io), 73 I/O54 3A4 (io), 74 I/O55 3A7 (io), 75 I/O56 3A8 (io), 76 I/O57 3A11 (io), 77 I/O58 3A12 (io), 78 I/O59 3A13 (io), 82 I/O60 4A2 (io), 83 I/O61 4A3 (io), 84 I/O62 4A4 (io), 85 I/O63 4A7 (io), 86 I/O64 4A8 (io), 87 I/O65 4A11 (io), 88 I/O66 4A12 (io), 89 I/O67 4A13 (io), 91 I/O68 4D13 (io), 92 I/O69 4D12 (io), 93 I/O70 4D11 (io), 94 I/O71 4D8 (io), 95 I/O72 4D7 (io), 96 I/O73 4D4 (io), 97 I/O74 4D3 (io), 98 I/O75 4D2 (io), 103 I/O76 5D2 (io), 104 I/O77 5D3 (io), 105 I/O78 5D4 (io), 106 I/O79 5D7 (io), 107 I/O80 5D8 (io), 108 I/O81 5D11 (io), 109 I/O82 5D12 (io), 110 I/O83 5D13 (io), 112 I/O84 5A13 (io), 113 I/O85 5A12 (io), 114 I/O86 5A11 (io), 115 I/O87 5A8 (io), 116 I/O88 5A7 (io), 117 I/O89 5A4 (io), 118 I/O90 5A3 (io), 119 I/O91 5A2 (io), 123 I/O92 6A13 (io), 124 I/O93 6A12 (io), 125 I/O94 6A11 (io), 126 I/O95 6A8 (io), 127 I/O96 6A7 (io), 128 I/O97 6A4 (io), 129 I/O98 6A3 (io), 130 I/O99 6A2 (io), 133 I/O100 6B3 (io), 134 I/O101 6B4 (io), 135 I/O102 6B7 (io), 136 I/O103 6B8 (io), 137 I/O104 6B11 (io), 138 I/O105 6B12 (io), 143 I/O106 7B12 (io), 144 I/O107 7B11 (io), 145 I/O108 7B8 (io), 146 I/O109 7B7 (io), 147 I/O110 7B4 (io), 148 I/O111 7B3 (io), 151 I/O112 7A2 (io), 152 I/O113 7A3 (io), 153 I/O114 7A4 (io), 154 I/O115 7A7 (io), 155 I/O116 7A8 (io), 156 I/O117 7A11 (io), 157 I/O118 7A12 (io), 158 I/O119 7A13 (io)
part B pins: 1 TDI (in), 10 GND (power), 19 I0/CLK0 (in), 20 VCC (power), 21 GND (power), 22 I1/CLK1 (in), 31 GND (power), 40 TCK (in), 41 GND (power), 42 VCC (power), 51 GND (power), 52 VCC (power), 59 VCC (power), 60 GND (power), 61 GND (power), 62 VCC (power), 69 VCC (power), 70 GND (power), 79 VCC (power), 80 GND (power), 81 TMS (in), 90 GND (power), 99 I2/CLK2 (in), 100 VCC (power), 101 GND (power), 102 I3/CLK3 (in), 111 GND (power), 120 TDO (out), 121 GND (power), 122 VCC (power), 131 GND (power), 132 VCC (power), 139 VCC (power), 140 GND (power), 141 GND (power), 142 VCC (power), 149 VCC (power), 150 GND (power), 159 VCC (power), 160 GND (power)

## M5LV-512/120-7HC
designator U?
High-Density and High-I/O Complex PLD
footprint MQFP160_N (QFP, 160-Leads, Body 27.7 x 27.7mm, Pitch 0.65mm, IPC Medium Density)
footprint MQFP160_L (QFP, 160-Leads, Body 27.7 x 27.7mm, Pitch 0.65mm, IPC High Density)
footprint MQFP160_M (QFP, 160-Leads, Body 27.7 x 27.7mm, Pitch 0.65mm, IPC Low Density)
3D model M5LV-MQFP160 (160-Pin Quad Flat Pack 0.65 mm Pitch)
part A pins: 2 I/O0 0A2 (io), 3 I/O1 0A3 (io), 4 I/O2 0A4 (io), 5 I/O3 0A7 (io), 6 I/O4 0A8 (io), 7 I/O5 0A11 (io), 8 I/O6 0A12 (io), 9 I/O7 0A13 (io), 11 I/O8 0D13 (io), 12 I/O9 0D12 (io), 13 I/O10 0D11 (io), 14 I/O11 0D8 (io), 15 I/O12 0D7 (io), 16 I/O13 0D4 (io), 17 I/O14 0D3 (io), 18 I/O15 0D2 (io), 23 I/O16 1D2 (io), 24 I/O17 1D3 (io), 25 I/O18 1D4 (io), 26 I/O19 1D7 (io), 27 I/O20 1D8 (io), 28 I/O21 1D11 (io), 29 I/O22 1D12 (io), 30 I/O23 1D13 (io), 32 I/O24 1A13 (io), 33 I/O25 1A12 (io), 34 I/O26 1A11 (io), 35 I/O27 1A8 (io), 36 I/O28 1A7 (io), 37 I/O29 1A4 (io), 38 I/O30 1A3 (io), 39 I/O31 1A2 (io), 43 I/O32 2A13 (io), 44 I/O33 2A12 (io), 45 I/O34 2A11 (io), 46 I/O35 2A8 (io), 47 I/O36 2A7 (io), 48 I/O37 2A4 (io), 49 I/O38 2A3 (io), 50 I/O39 2A2 (io), 53 I/O40 2B3 (io), 54 I/O41 2B4 (io), 55 I/O42 2B7 (io), 56 I/O43 2B8 (io), 57 I/O44 2B11 (io), 58 I/O45 2B12 (io), 63 I/O46 3B12 (io), 64 I/O47 3B11 (io), 65 I/O48 3B8 (io), 66 I/O49 3B7 (io), 67 I/O50 3B4 (io), 68 I/O51 3B3 (io), 71 I/O52 3A2 (io), 72 I/O53 3A3 (io), 73 I/O54 3A4 (io), 74 I/O55 3A7 (io), 75 I/O56 3A8 (io), 76 I/O57 3A11 (io), 77 I/O58 3A12 (io), 78 I/O59 3A13 (io), 82 I/O60 4A2 (io), 83 I/O61 4A3 (io), 84 I/O62 4A4 (io), 85 I/O63 4A7 (io), 86 I/O64 4A8 (io), 87 I/O65 4A11 (io), 88 I/O66 4A12 (io), 89 I/O67 4A13 (io), 91 I/O68 4D13 (io), 92 I/O69 4D12 (io), 93 I/O70 4D11 (io), 94 I/O71 4D8 (io), 95 I/O72 4D7 (io), 96 I/O73 4D4 (io), 97 I/O74 4D3 (io), 98 I/O75 4D2 (io), 103 I/O76 5D2 (io), 104 I/O77 5D3 (io), 105 I/O78 5D4 (io), 106 I/O79 5D7 (io), 107 I/O80 5D8 (io), 108 I/O81 5D11 (io), 109 I/O82 5D12 (io), 110 I/O83 5D13 (io), 112 I/O84 5A13 (io), 113 I/O85 5A12 (io), 114 I/O86 5A11 (io), 115 I/O87 5A8 (io), 116 I/O88 5A7 (io), 117 I/O89 5A4 (io), 118 I/O90 5A3 (io), 119 I/O91 5A2 (io), 123 I/O92 6A13 (io), 124 I/O93 6A12 (io), 125 I/O94 6A11 (io), 126 I/O95 6A8 (io), 127 I/O96 6A7 (io), 128 I/O97 6A4 (io), 129 I/O98 6A3 (io), 130 I/O99 6A2 (io), 133 I/O100 6B3 (io), 134 I/O101 6B4 (io), 135 I/O102 6B7 (io), 136 I/O103 6B8 (io), 137 I/O104 6B11 (io), 138 I/O105 6B12 (io), 143 I/O106 7B12 (io), 144 I/O107 7B11 (io), 145 I/O108 7B8 (io), 146 I/O109 7B7 (io), 147 I/O110 7B4 (io), 148 I/O111 7B3 (io), 151 I/O112 7A2 (io), 152 I/O113 7A3 (io), 153 I/O114 7A4 (io), 154 I/O115 7A7 (io), 155 I/O116 7A8 (io), 156 I/O117 7A11 (io), 157 I/O118 7A12 (io), 158 I/O119 7A13 (io)
part B pins: 1 TDI (in), 10 GND (power), 19 I0/CLK0 (in), 20 VCC (power), 21 GND (power), 22 I1/CLK1 (in), 31 GND (power), 40 TCK (in), 41 GND (power), 42 VCC (power), 51 GND (power), 52 VCC (power), 59 VCC (power), 60 GND (power), 61 GND (power), 62 VCC (power), 69 VCC (power), 70 GND (power), 79 VCC (power), 80 GND (power), 81 TMS (in), 90 GND (power), 99 I2/CLK2 (in), 100 VCC (power), 101 GND (power), 102 I3/CLK3 (in), 111 GND (power), 120 TDO (out), 121 GND (power), 122 VCC (power), 131 GND (power), 132 VCC (power), 139 VCC (power), 140 GND (power), 141 GND (power), 142 VCC (power), 149 VCC (power), 150 GND (power), 159 VCC (power), 160 GND (power)

## M5LV-512/120-10HC
designator U?
High-Density and High-I/O Complex PLD
footprint MQFP160_N (QFP, 160-Leads, Body 27.7 x 27.7mm, Pitch 0.65mm, IPC Medium Density)
footprint MQFP160_L (QFP, 160-Leads, Body 27.7 x 27.7mm, Pitch 0.65mm, IPC High Density)
footprint MQFP160_M (QFP, 160-Leads, Body 27.7 x 27.7mm, Pitch 0.65mm, IPC Low Density)
3D model M5LV-MQFP160 (160-Pin Quad Flat Pack 0.65 mm Pitch)
part A pins: 2 I/O0 0A2 (io), 3 I/O1 0A3 (io), 4 I/O2 0A4 (io), 5 I/O3 0A7 (io), 6 I/O4 0A8 (io), 7 I/O5 0A11 (io), 8 I/O6 0A12 (io), 9 I/O7 0A13 (io), 11 I/O8 0D13 (io), 12 I/O9 0D12 (io), 13 I/O10 0D11 (io), 14 I/O11 0D8 (io), 15 I/O12 0D7 (io), 16 I/O13 0D4 (io), 17 I/O14 0D3 (io), 18 I/O15 0D2 (io), 23 I/O16 1D2 (io), 24 I/O17 1D3 (io), 25 I/O18 1D4 (io), 26 I/O19 1D7 (io), 27 I/O20 1D8 (io), 28 I/O21 1D11 (io), 29 I/O22 1D12 (io), 30 I/O23 1D13 (io), 32 I/O24 1A13 (io), 33 I/O25 1A12 (io), 34 I/O26 1A11 (io), 35 I/O27 1A8 (io), 36 I/O28 1A7 (io), 37 I/O29 1A4 (io), 38 I/O30 1A3 (io), 39 I/O31 1A2 (io), 43 I/O32 2A13 (io), 44 I/O33 2A12 (io), 45 I/O34 2A11 (io), 46 I/O35 2A8 (io), 47 I/O36 2A7 (io), 48 I/O37 2A4 (io), 49 I/O38 2A3 (io), 50 I/O39 2A2 (io), 53 I/O40 2B3 (io), 54 I/O41 2B4 (io), 55 I/O42 2B7 (io), 56 I/O43 2B8 (io), 57 I/O44 2B11 (io), 58 I/O45 2B12 (io), 63 I/O46 3B12 (io), 64 I/O47 3B11 (io), 65 I/O48 3B8 (io), 66 I/O49 3B7 (io), 67 I/O50 3B4 (io), 68 I/O51 3B3 (io), 71 I/O52 3A2 (io), 72 I/O53 3A3 (io), 73 I/O54 3A4 (io), 74 I/O55 3A7 (io), 75 I/O56 3A8 (io), 76 I/O57 3A11 (io), 77 I/O58 3A12 (io), 78 I/O59 3A13 (io), 82 I/O60 4A2 (io), 83 I/O61 4A3 (io), 84 I/O62 4A4 (io), 85 I/O63 4A7 (io), 86 I/O64 4A8 (io), 87 I/O65 4A11 (io), 88 I/O66 4A12 (io), 89 I/O67 4A13 (io), 91 I/O68 4D13 (io), 92 I/O69 4D12 (io), 93 I/O70 4D11 (io), 94 I/O71 4D8 (io), 95 I/O72 4D7 (io), 96 I/O73 4D4 (io), 97 I/O74 4D3 (io), 98 I/O75 4D2 (io), 103 I/O76 5D2 (io), 104 I/O77 5D3 (io), 105 I/O78 5D4 (io), 106 I/O79 5D7 (io), 107 I/O80 5D8 (io), 108 I/O81 5D11 (io), 109 I/O82 5D12 (io), 110 I/O83 5D13 (io), 112 I/O84 5A13 (io), 113 I/O85 5A12 (io), 114 I/O86 5A11 (io), 115 I/O87 5A8 (io), 116 I/O88 5A7 (io), 117 I/O89 5A4 (io), 118 I/O90 5A3 (io), 119 I/O91 5A2 (io), 123 I/O92 6A13 (io), 124 I/O93 6A12 (io), 125 I/O94 6A11 (io), 126 I/O95 6A8 (io), 127 I/O96 6A7 (io), 128 I/O97 6A4 (io), 129 I/O98 6A3 (io), 130 I/O99 6A2 (io), 133 I/O100 6B3 (io), 134 I/O101 6B4 (io), 135 I/O102 6B7 (io), 136 I/O103 6B8 (io), 137 I/O104 6B11 (io), 138 I/O105 6B12 (io), 143 I/O106 7B12 (io), 144 I/O107 7B11 (io), 145 I/O108 7B8 (io), 146 I/O109 7B7 (io), 147 I/O110 7B4 (io), 148 I/O111 7B3 (io), 151 I/O112 7A2 (io), 152 I/O113 7A3 (io), 153 I/O114 7A4 (io), 154 I/O115 7A7 (io), 155 I/O116 7A8 (io), 156 I/O117 7A11 (io), 157 I/O118 7A12 (io), 158 I/O119 7A13 (io)
part B pins: 1 TDI (in), 10 GND (power), 19 I0/CLK0 (in), 20 VCC (power), 21 GND (power), 22 I1/CLK1 (in), 31 GND (power), 40 TCK (in), 41 GND (power), 42 VCC (power), 51 GND (power), 52 VCC (power), 59 VCC (power), 60 GND (power), 61 GND (power), 62 VCC (power), 69 VCC (power), 70 GND (power), 79 VCC (power), 80 GND (power), 81 TMS (in), 90 GND (power), 99 I2/CLK2 (in), 100 VCC (power), 101 GND (power), 102 I3/CLK3 (in), 111 GND (power), 120 TDO (out), 121 GND (power), 122 VCC (power), 131 GND (power), 132 VCC (power), 139 VCC (power), 140 GND (power), 141 GND (power), 142 VCC (power), 149 VCC (power), 150 GND (power), 159 VCC (power), 160 GND (power)

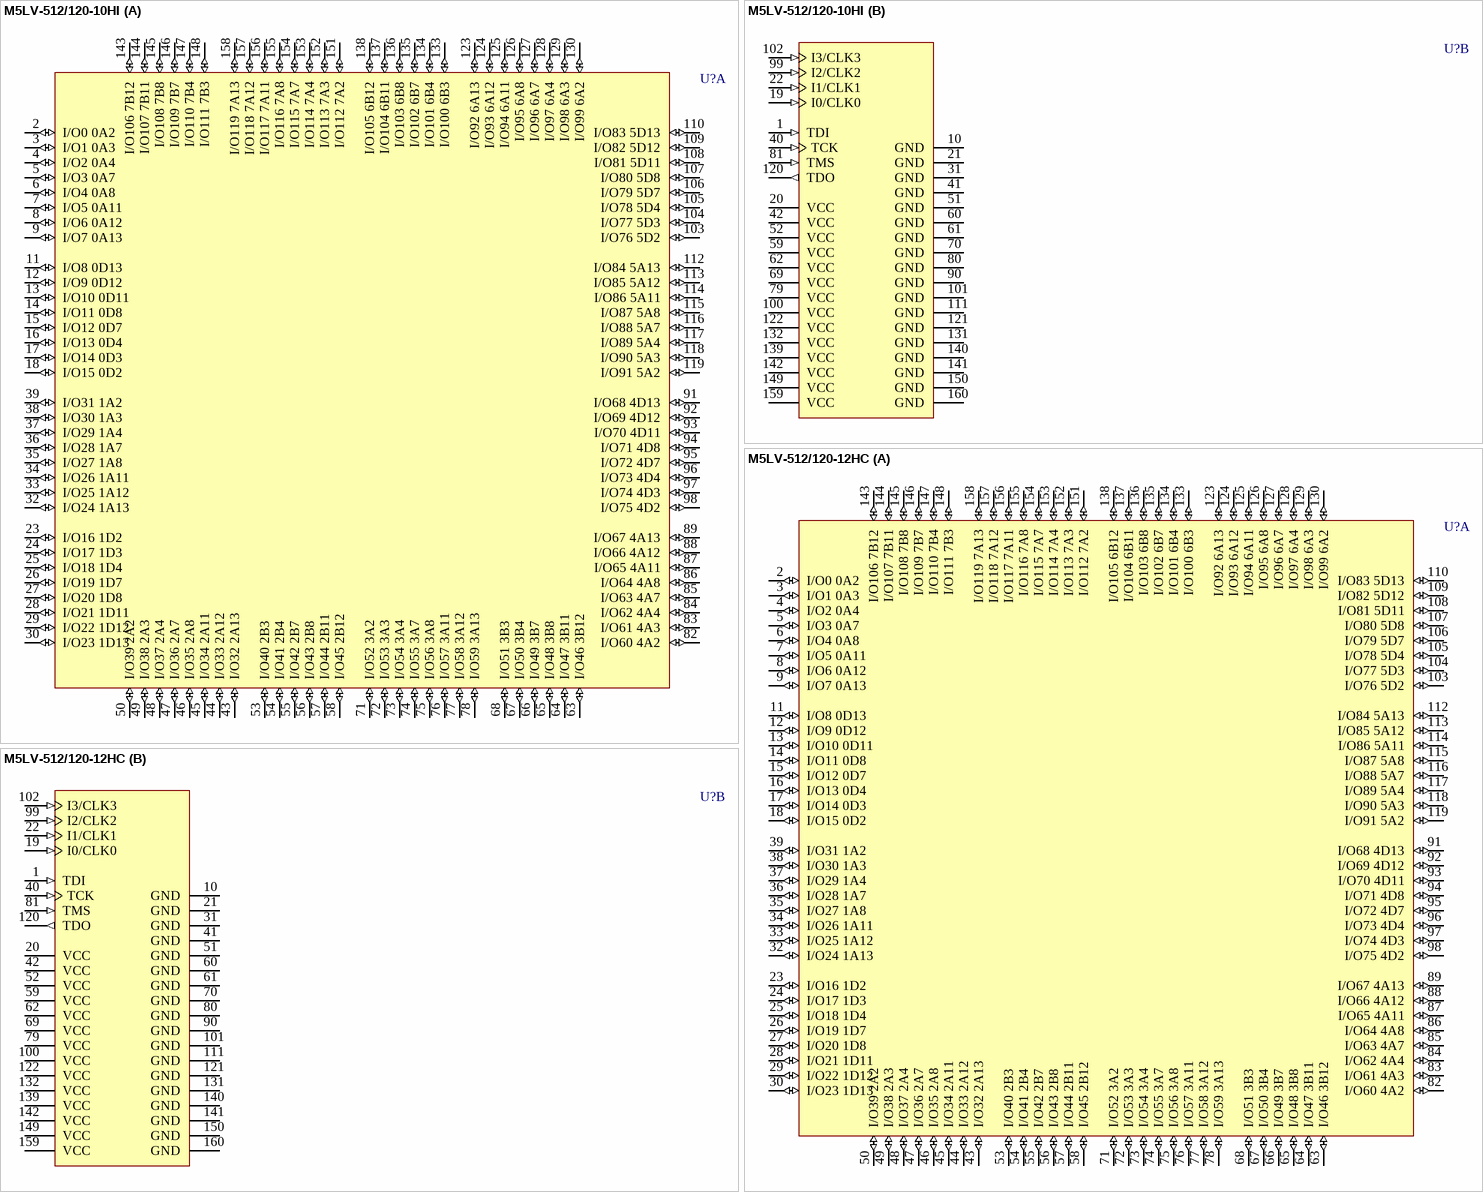
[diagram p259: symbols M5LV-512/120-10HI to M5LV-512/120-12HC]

## M5LV-512/120-10HI
designator U?
High-Density and High-I/O Complex PLD
footprint MQFP160_N (QFP, 160-Leads, Body 27.7 x 27.7mm, Pitch 0.65mm, IPC Medium Density)
footprint MQFP160_L (QFP, 160-Leads, Body 27.7 x 27.7mm, Pitch 0.65mm, IPC High Density)
footprint MQFP160_M (QFP, 160-Leads, Body 27.7 x 27.7mm, Pitch 0.65mm, IPC Low Density)
3D model M5LV-MQFP160 (160-Pin Quad Flat Pack 0.65 mm Pitch)
part A pins: 2 I/O0 0A2 (io), 3 I/O1 0A3 (io), 4 I/O2 0A4 (io), 5 I/O3 0A7 (io), 6 I/O4 0A8 (io), 7 I/O5 0A11 (io), 8 I/O6 0A12 (io), 9 I/O7 0A13 (io), 11 I/O8 0D13 (io), 12 I/O9 0D12 (io), 13 I/O10 0D11 (io), 14 I/O11 0D8 (io), 15 I/O12 0D7 (io), 16 I/O13 0D4 (io), 17 I/O14 0D3 (io), 18 I/O15 0D2 (io), 23 I/O16 1D2 (io), 24 I/O17 1D3 (io), 25 I/O18 1D4 (io), 26 I/O19 1D7 (io), 27 I/O20 1D8 (io), 28 I/O21 1D11 (io), 29 I/O22 1D12 (io), 30 I/O23 1D13 (io), 32 I/O24 1A13 (io), 33 I/O25 1A12 (io), 34 I/O26 1A11 (io), 35 I/O27 1A8 (io), 36 I/O28 1A7 (io), 37 I/O29 1A4 (io), 38 I/O30 1A3 (io), 39 I/O31 1A2 (io), 43 I/O32 2A13 (io), 44 I/O33 2A12 (io), 45 I/O34 2A11 (io), 46 I/O35 2A8 (io), 47 I/O36 2A7 (io), 48 I/O37 2A4 (io), 49 I/O38 2A3 (io), 50 I/O39 2A2 (io), 53 I/O40 2B3 (io), 54 I/O41 2B4 (io), 55 I/O42 2B7 (io), 56 I/O43 2B8 (io), 57 I/O44 2B11 (io), 58 I/O45 2B12 (io), 63 I/O46 3B12 (io), 64 I/O47 3B11 (io), 65 I/O48 3B8 (io), 66 I/O49 3B7 (io), 67 I/O50 3B4 (io), 68 I/O51 3B3 (io), 71 I/O52 3A2 (io), 72 I/O53 3A3 (io), 73 I/O54 3A4 (io), 74 I/O55 3A7 (io), 75 I/O56 3A8 (io), 76 I/O57 3A11 (io), 77 I/O58 3A12 (io), 78 I/O59 3A13 (io), 82 I/O60 4A2 (io), 83 I/O61 4A3 (io), 84 I/O62 4A4 (io), 85 I/O63 4A7 (io), 86 I/O64 4A8 (io), 87 I/O65 4A11 (io), 88 I/O66 4A12 (io), 89 I/O67 4A13 (io), 91 I/O68 4D13 (io), 92 I/O69 4D12 (io), 93 I/O70 4D11 (io), 94 I/O71 4D8 (io), 95 I/O72 4D7 (io), 96 I/O73 4D4 (io), 97 I/O74 4D3 (io), 98 I/O75 4D2 (io), 103 I/O76 5D2 (io), 104 I/O77 5D3 (io), 105 I/O78 5D4 (io), 106 I/O79 5D7 (io), 107 I/O80 5D8 (io), 108 I/O81 5D11 (io), 109 I/O82 5D12 (io), 110 I/O83 5D13 (io), 112 I/O84 5A13 (io), 113 I/O85 5A12 (io), 114 I/O86 5A11 (io), 115 I/O87 5A8 (io), 116 I/O88 5A7 (io), 117 I/O89 5A4 (io), 118 I/O90 5A3 (io), 119 I/O91 5A2 (io), 123 I/O92 6A13 (io), 124 I/O93 6A12 (io), 125 I/O94 6A11 (io), 126 I/O95 6A8 (io), 127 I/O96 6A7 (io), 128 I/O97 6A4 (io), 129 I/O98 6A3 (io), 130 I/O99 6A2 (io), 133 I/O100 6B3 (io), 134 I/O101 6B4 (io), 135 I/O102 6B7 (io), 136 I/O103 6B8 (io), 137 I/O104 6B11 (io), 138 I/O105 6B12 (io), 143 I/O106 7B12 (io), 144 I/O107 7B11 (io), 145 I/O108 7B8 (io), 146 I/O109 7B7 (io), 147 I/O110 7B4 (io), 148 I/O111 7B3 (io), 151 I/O112 7A2 (io), 152 I/O113 7A3 (io), 153 I/O114 7A4 (io), 154 I/O115 7A7 (io), 155 I/O116 7A8 (io), 156 I/O117 7A11 (io), 157 I/O118 7A12 (io), 158 I/O119 7A13 (io)
part B pins: 1 TDI (in), 10 GND (power), 19 I0/CLK0 (in), 20 VCC (power), 21 GND (power), 22 I1/CLK1 (in), 31 GND (power), 40 TCK (in), 41 GND (power), 42 VCC (power), 51 GND (power), 52 VCC (power), 59 VCC (power), 60 GND (power), 61 GND (power), 62 VCC (power), 69 VCC (power), 70 GND (power), 79 VCC (power), 80 GND (power), 81 TMS (in), 90 GND (power), 99 I2/CLK2 (in), 100 VCC (power), 101 GND (power), 102 I3/CLK3 (in), 111 GND (power), 120 TDO (out), 121 GND (power), 122 VCC (power), 131 GND (power), 132 VCC (power), 139 VCC (power), 140 GND (power), 141 GND (power), 142 VCC (power), 149 VCC (power), 150 GND (power), 159 VCC (power), 160 GND (power)

## M5LV-512/120-12HC
designator U?
High-Density and High-I/O Complex PLD
footprint MQFP160_N (QFP, 160-Leads, Body 27.7 x 27.7mm, Pitch 0.65mm, IPC Medium Density)
footprint MQFP160_L (QFP, 160-Leads, Body 27.7 x 27.7mm, Pitch 0.65mm, IPC High Density)
footprint MQFP160_M (QFP, 160-Leads, Body 27.7 x 27.7mm, Pitch 0.65mm, IPC Low Density)
3D model M5LV-MQFP160 (160-Pin Quad Flat Pack 0.65 mm Pitch)
part A pins: 2 I/O0 0A2 (io), 3 I/O1 0A3 (io), 4 I/O2 0A4 (io), 5 I/O3 0A7 (io), 6 I/O4 0A8 (io), 7 I/O5 0A11 (io), 8 I/O6 0A12 (io), 9 I/O7 0A13 (io), 11 I/O8 0D13 (io), 12 I/O9 0D12 (io), 13 I/O10 0D11 (io), 14 I/O11 0D8 (io), 15 I/O12 0D7 (io), 16 I/O13 0D4 (io), 17 I/O14 0D3 (io), 18 I/O15 0D2 (io), 23 I/O16 1D2 (io), 24 I/O17 1D3 (io), 25 I/O18 1D4 (io), 26 I/O19 1D7 (io), 27 I/O20 1D8 (io), 28 I/O21 1D11 (io), 29 I/O22 1D12 (io), 30 I/O23 1D13 (io), 32 I/O24 1A13 (io), 33 I/O25 1A12 (io), 34 I/O26 1A11 (io), 35 I/O27 1A8 (io), 36 I/O28 1A7 (io), 37 I/O29 1A4 (io), 38 I/O30 1A3 (io), 39 I/O31 1A2 (io), 43 I/O32 2A13 (io), 44 I/O33 2A12 (io), 45 I/O34 2A11 (io), 46 I/O35 2A8 (io), 47 I/O36 2A7 (io), 48 I/O37 2A4 (io), 49 I/O38 2A3 (io), 50 I/O39 2A2 (io), 53 I/O40 2B3 (io), 54 I/O41 2B4 (io), 55 I/O42 2B7 (io), 56 I/O43 2B8 (io), 57 I/O44 2B11 (io), 58 I/O45 2B12 (io), 63 I/O46 3B12 (io), 64 I/O47 3B11 (io), 65 I/O48 3B8 (io), 66 I/O49 3B7 (io), 67 I/O50 3B4 (io), 68 I/O51 3B3 (io), 71 I/O52 3A2 (io), 72 I/O53 3A3 (io), 73 I/O54 3A4 (io), 74 I/O55 3A7 (io), 75 I/O56 3A8 (io), 76 I/O57 3A11 (io), 77 I/O58 3A12 (io), 78 I/O59 3A13 (io), 82 I/O60 4A2 (io), 83 I/O61 4A3 (io), 84 I/O62 4A4 (io), 85 I/O63 4A7 (io), 86 I/O64 4A8 (io), 87 I/O65 4A11 (io), 88 I/O66 4A12 (io), 89 I/O67 4A13 (io), 91 I/O68 4D13 (io), 92 I/O69 4D12 (io), 93 I/O70 4D11 (io), 94 I/O71 4D8 (io), 95 I/O72 4D7 (io), 96 I/O73 4D4 (io), 97 I/O74 4D3 (io), 98 I/O75 4D2 (io), 103 I/O76 5D2 (io), 104 I/O77 5D3 (io), 105 I/O78 5D4 (io), 106 I/O79 5D7 (io), 107 I/O80 5D8 (io), 108 I/O81 5D11 (io), 109 I/O82 5D12 (io), 110 I/O83 5D13 (io), 112 I/O84 5A13 (io), 113 I/O85 5A12 (io), 114 I/O86 5A11 (io), 115 I/O87 5A8 (io), 116 I/O88 5A7 (io), 117 I/O89 5A4 (io), 118 I/O90 5A3 (io), 119 I/O91 5A2 (io), 123 I/O92 6A13 (io), 124 I/O93 6A12 (io), 125 I/O94 6A11 (io), 126 I/O95 6A8 (io), 127 I/O96 6A7 (io), 128 I/O97 6A4 (io), 129 I/O98 6A3 (io), 130 I/O99 6A2 (io), 133 I/O100 6B3 (io), 134 I/O101 6B4 (io), 135 I/O102 6B7 (io), 136 I/O103 6B8 (io), 137 I/O104 6B11 (io), 138 I/O105 6B12 (io), 143 I/O106 7B12 (io), 144 I/O107 7B11 (io), 145 I/O108 7B8 (io), 146 I/O109 7B7 (io), 147 I/O110 7B4 (io), 148 I/O111 7B3 (io), 151 I/O112 7A2 (io), 152 I/O113 7A3 (io), 153 I/O114 7A4 (io), 154 I/O115 7A7 (io), 155 I/O116 7A8 (io), 156 I/O117 7A11 (io), 157 I/O118 7A12 (io), 158 I/O119 7A13 (io)
part B pins: 1 TDI (in), 10 GND (power), 19 I0/CLK0 (in), 20 VCC (power), 21 GND (power), 22 I1/CLK1 (in), 31 GND (power), 40 TCK (in), 41 GND (power), 42 VCC (power), 51 GND (power), 52 VCC (power), 59 VCC (power), 60 GND (power), 61 GND (power), 62 VCC (power), 69 VCC (power), 70 GND (power), 79 VCC (power), 80 GND (power), 81 TMS (in), 90 GND (power), 99 I2/CLK2 (in), 100 VCC (power), 101 GND (power), 102 I3/CLK3 (in), 111 GND (power), 120 TDO (out), 121 GND (power), 122 VCC (power), 131 GND (power), 132 VCC (power), 139 VCC (power), 140 GND (power), 141 GND (power), 142 VCC (power), 149 VCC (power), 150 GND (power), 159 VCC (power), 160 GND (power)

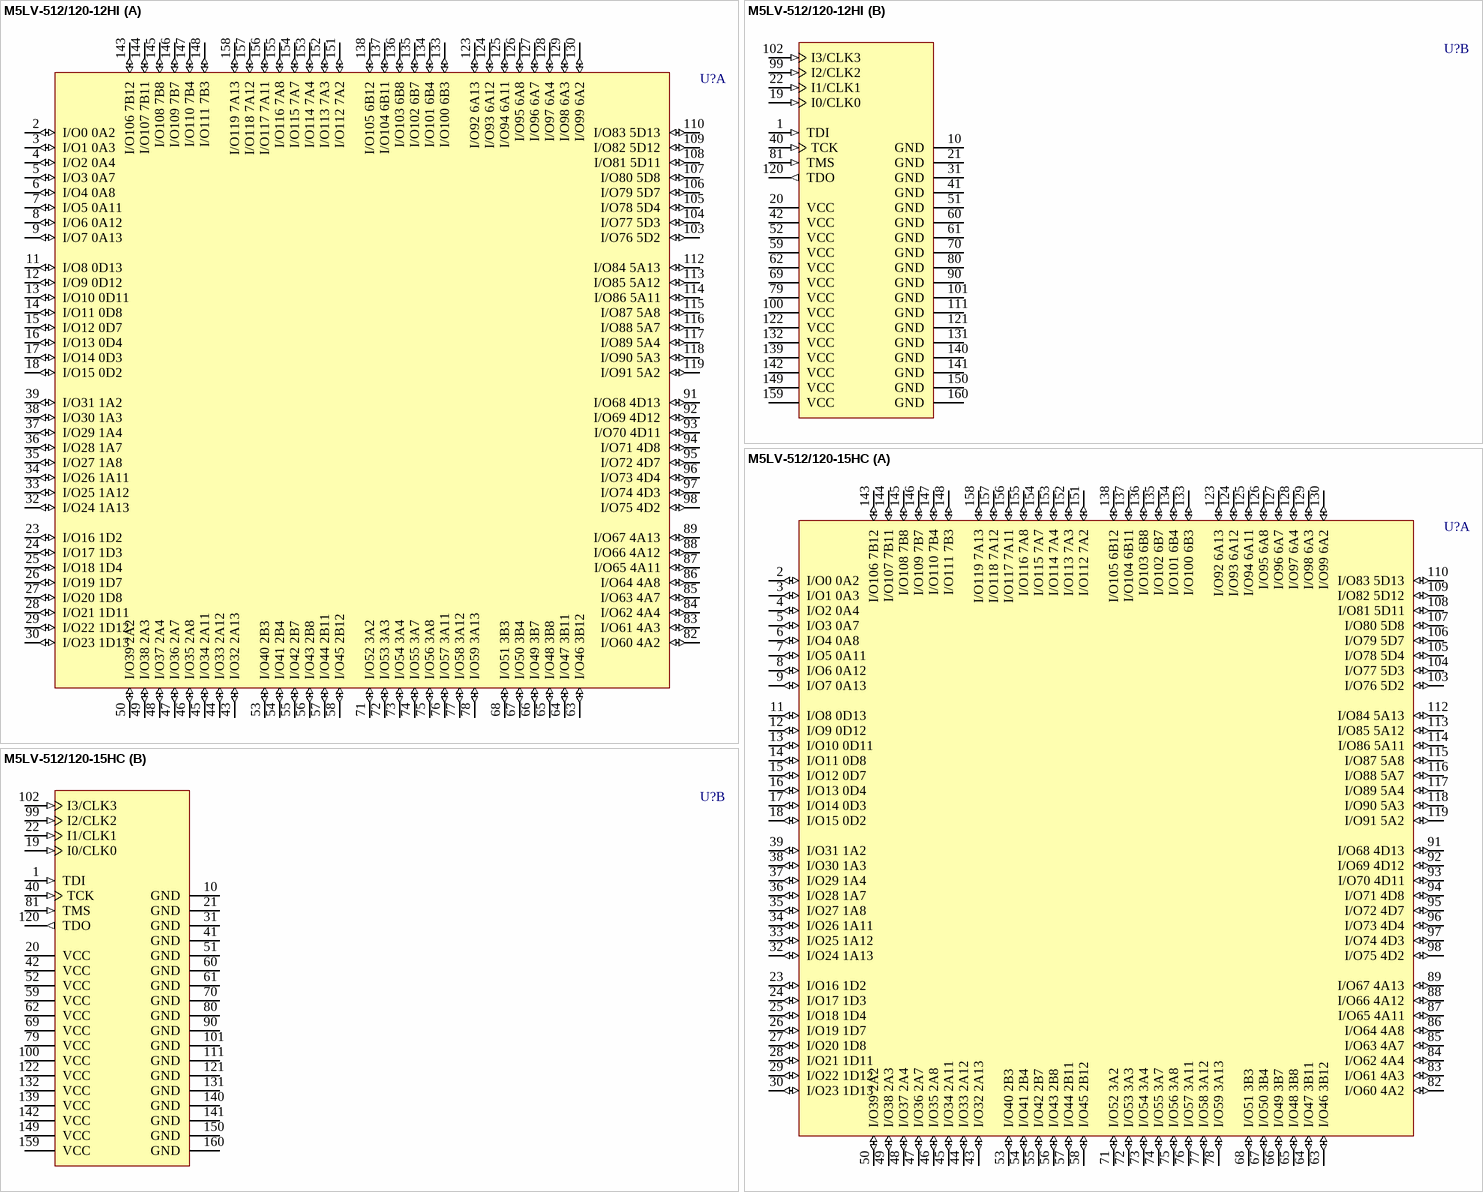
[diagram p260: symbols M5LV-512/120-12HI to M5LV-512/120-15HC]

## M5LV-512/120-12HI
designator U?
High-Density and High-I/O Complex PLD
footprint MQFP160_N (QFP, 160-Leads, Body 27.7 x 27.7mm, Pitch 0.65mm, IPC Medium Density)
footprint MQFP160_L (QFP, 160-Leads, Body 27.7 x 27.7mm, Pitch 0.65mm, IPC High Density)
footprint MQFP160_M (QFP, 160-Leads, Body 27.7 x 27.7mm, Pitch 0.65mm, IPC Low Density)
3D model M5LV-MQFP160 (160-Pin Quad Flat Pack 0.65 mm Pitch)
part A pins: 2 I/O0 0A2 (io), 3 I/O1 0A3 (io), 4 I/O2 0A4 (io), 5 I/O3 0A7 (io), 6 I/O4 0A8 (io), 7 I/O5 0A11 (io), 8 I/O6 0A12 (io), 9 I/O7 0A13 (io), 11 I/O8 0D13 (io), 12 I/O9 0D12 (io), 13 I/O10 0D11 (io), 14 I/O11 0D8 (io), 15 I/O12 0D7 (io), 16 I/O13 0D4 (io), 17 I/O14 0D3 (io), 18 I/O15 0D2 (io), 23 I/O16 1D2 (io), 24 I/O17 1D3 (io), 25 I/O18 1D4 (io), 26 I/O19 1D7 (io), 27 I/O20 1D8 (io), 28 I/O21 1D11 (io), 29 I/O22 1D12 (io), 30 I/O23 1D13 (io), 32 I/O24 1A13 (io), 33 I/O25 1A12 (io), 34 I/O26 1A11 (io), 35 I/O27 1A8 (io), 36 I/O28 1A7 (io), 37 I/O29 1A4 (io), 38 I/O30 1A3 (io), 39 I/O31 1A2 (io), 43 I/O32 2A13 (io), 44 I/O33 2A12 (io), 45 I/O34 2A11 (io), 46 I/O35 2A8 (io), 47 I/O36 2A7 (io), 48 I/O37 2A4 (io), 49 I/O38 2A3 (io), 50 I/O39 2A2 (io), 53 I/O40 2B3 (io), 54 I/O41 2B4 (io), 55 I/O42 2B7 (io), 56 I/O43 2B8 (io), 57 I/O44 2B11 (io), 58 I/O45 2B12 (io), 63 I/O46 3B12 (io), 64 I/O47 3B11 (io), 65 I/O48 3B8 (io), 66 I/O49 3B7 (io), 67 I/O50 3B4 (io), 68 I/O51 3B3 (io), 71 I/O52 3A2 (io), 72 I/O53 3A3 (io), 73 I/O54 3A4 (io), 74 I/O55 3A7 (io), 75 I/O56 3A8 (io), 76 I/O57 3A11 (io), 77 I/O58 3A12 (io), 78 I/O59 3A13 (io), 82 I/O60 4A2 (io), 83 I/O61 4A3 (io), 84 I/O62 4A4 (io), 85 I/O63 4A7 (io), 86 I/O64 4A8 (io), 87 I/O65 4A11 (io), 88 I/O66 4A12 (io), 89 I/O67 4A13 (io), 91 I/O68 4D13 (io), 92 I/O69 4D12 (io), 93 I/O70 4D11 (io), 94 I/O71 4D8 (io), 95 I/O72 4D7 (io), 96 I/O73 4D4 (io), 97 I/O74 4D3 (io), 98 I/O75 4D2 (io), 103 I/O76 5D2 (io), 104 I/O77 5D3 (io), 105 I/O78 5D4 (io), 106 I/O79 5D7 (io), 107 I/O80 5D8 (io), 108 I/O81 5D11 (io), 109 I/O82 5D12 (io), 110 I/O83 5D13 (io), 112 I/O84 5A13 (io), 113 I/O85 5A12 (io), 114 I/O86 5A11 (io), 115 I/O87 5A8 (io), 116 I/O88 5A7 (io), 117 I/O89 5A4 (io), 118 I/O90 5A3 (io), 119 I/O91 5A2 (io), 123 I/O92 6A13 (io), 124 I/O93 6A12 (io), 125 I/O94 6A11 (io), 126 I/O95 6A8 (io), 127 I/O96 6A7 (io), 128 I/O97 6A4 (io), 129 I/O98 6A3 (io), 130 I/O99 6A2 (io), 133 I/O100 6B3 (io), 134 I/O101 6B4 (io), 135 I/O102 6B7 (io), 136 I/O103 6B8 (io), 137 I/O104 6B11 (io), 138 I/O105 6B12 (io), 143 I/O106 7B12 (io), 144 I/O107 7B11 (io), 145 I/O108 7B8 (io), 146 I/O109 7B7 (io), 147 I/O110 7B4 (io), 148 I/O111 7B3 (io), 151 I/O112 7A2 (io), 152 I/O113 7A3 (io), 153 I/O114 7A4 (io), 154 I/O115 7A7 (io), 155 I/O116 7A8 (io), 156 I/O117 7A11 (io), 157 I/O118 7A12 (io), 158 I/O119 7A13 (io)
part B pins: 1 TDI (in), 10 GND (power), 19 I0/CLK0 (in), 20 VCC (power), 21 GND (power), 22 I1/CLK1 (in), 31 GND (power), 40 TCK (in), 41 GND (power), 42 VCC (power), 51 GND (power), 52 VCC (power), 59 VCC (power), 60 GND (power), 61 GND (power), 62 VCC (power), 69 VCC (power), 70 GND (power), 79 VCC (power), 80 GND (power), 81 TMS (in), 90 GND (power), 99 I2/CLK2 (in), 100 VCC (power), 101 GND (power), 102 I3/CLK3 (in), 111 GND (power), 120 TDO (out), 121 GND (power), 122 VCC (power), 131 GND (power), 132 VCC (power), 139 VCC (power), 140 GND (power), 141 GND (power), 142 VCC (power), 149 VCC (power), 150 GND (power), 159 VCC (power), 160 GND (power)

## M5LV-512/120-15HC
designator U?
High-Density and High-I/O Complex PLD
footprint MQFP160_N (QFP, 160-Leads, Body 27.7 x 27.7mm, Pitch 0.65mm, IPC Medium Density)
footprint MQFP160_L (QFP, 160-Leads, Body 27.7 x 27.7mm, Pitch 0.65mm, IPC High Density)
footprint MQFP160_M (QFP, 160-Leads, Body 27.7 x 27.7mm, Pitch 0.65mm, IPC Low Density)
3D model M5LV-MQFP160 (160-Pin Quad Flat Pack 0.65 mm Pitch)
part A pins: 2 I/O0 0A2 (io), 3 I/O1 0A3 (io), 4 I/O2 0A4 (io), 5 I/O3 0A7 (io), 6 I/O4 0A8 (io), 7 I/O5 0A11 (io), 8 I/O6 0A12 (io), 9 I/O7 0A13 (io), 11 I/O8 0D13 (io), 12 I/O9 0D12 (io), 13 I/O10 0D11 (io), 14 I/O11 0D8 (io), 15 I/O12 0D7 (io), 16 I/O13 0D4 (io), 17 I/O14 0D3 (io), 18 I/O15 0D2 (io), 23 I/O16 1D2 (io), 24 I/O17 1D3 (io), 25 I/O18 1D4 (io), 26 I/O19 1D7 (io), 27 I/O20 1D8 (io), 28 I/O21 1D11 (io), 29 I/O22 1D12 (io), 30 I/O23 1D13 (io), 32 I/O24 1A13 (io), 33 I/O25 1A12 (io), 34 I/O26 1A11 (io), 35 I/O27 1A8 (io), 36 I/O28 1A7 (io), 37 I/O29 1A4 (io), 38 I/O30 1A3 (io), 39 I/O31 1A2 (io), 43 I/O32 2A13 (io), 44 I/O33 2A12 (io), 45 I/O34 2A11 (io), 46 I/O35 2A8 (io), 47 I/O36 2A7 (io), 48 I/O37 2A4 (io), 49 I/O38 2A3 (io), 50 I/O39 2A2 (io), 53 I/O40 2B3 (io), 54 I/O41 2B4 (io), 55 I/O42 2B7 (io), 56 I/O43 2B8 (io), 57 I/O44 2B11 (io), 58 I/O45 2B12 (io), 63 I/O46 3B12 (io), 64 I/O47 3B11 (io), 65 I/O48 3B8 (io), 66 I/O49 3B7 (io), 67 I/O50 3B4 (io), 68 I/O51 3B3 (io), 71 I/O52 3A2 (io), 72 I/O53 3A3 (io), 73 I/O54 3A4 (io), 74 I/O55 3A7 (io), 75 I/O56 3A8 (io), 76 I/O57 3A11 (io), 77 I/O58 3A12 (io), 78 I/O59 3A13 (io), 82 I/O60 4A2 (io), 83 I/O61 4A3 (io), 84 I/O62 4A4 (io), 85 I/O63 4A7 (io), 86 I/O64 4A8 (io), 87 I/O65 4A11 (io), 88 I/O66 4A12 (io), 89 I/O67 4A13 (io), 91 I/O68 4D13 (io), 92 I/O69 4D12 (io), 93 I/O70 4D11 (io), 94 I/O71 4D8 (io), 95 I/O72 4D7 (io), 96 I/O73 4D4 (io), 97 I/O74 4D3 (io), 98 I/O75 4D2 (io), 103 I/O76 5D2 (io), 104 I/O77 5D3 (io), 105 I/O78 5D4 (io), 106 I/O79 5D7 (io), 107 I/O80 5D8 (io), 108 I/O81 5D11 (io), 109 I/O82 5D12 (io), 110 I/O83 5D13 (io), 112 I/O84 5A13 (io), 113 I/O85 5A12 (io), 114 I/O86 5A11 (io), 115 I/O87 5A8 (io), 116 I/O88 5A7 (io), 117 I/O89 5A4 (io), 118 I/O90 5A3 (io), 119 I/O91 5A2 (io), 123 I/O92 6A13 (io), 124 I/O93 6A12 (io), 125 I/O94 6A11 (io), 126 I/O95 6A8 (io), 127 I/O96 6A7 (io), 128 I/O97 6A4 (io), 129 I/O98 6A3 (io), 130 I/O99 6A2 (io), 133 I/O100 6B3 (io), 134 I/O101 6B4 (io), 135 I/O102 6B7 (io), 136 I/O103 6B8 (io), 137 I/O104 6B11 (io), 138 I/O105 6B12 (io), 143 I/O106 7B12 (io), 144 I/O107 7B11 (io), 145 I/O108 7B8 (io), 146 I/O109 7B7 (io), 147 I/O110 7B4 (io), 148 I/O111 7B3 (io), 151 I/O112 7A2 (io), 152 I/O113 7A3 (io), 153 I/O114 7A4 (io), 154 I/O115 7A7 (io), 155 I/O116 7A8 (io), 156 I/O117 7A11 (io), 157 I/O118 7A12 (io), 158 I/O119 7A13 (io)
part B pins: 1 TDI (in), 10 GND (power), 19 I0/CLK0 (in), 20 VCC (power), 21 GND (power), 22 I1/CLK1 (in), 31 GND (power), 40 TCK (in), 41 GND (power), 42 VCC (power), 51 GND (power), 52 VCC (power), 59 VCC (power), 60 GND (power), 61 GND (power), 62 VCC (power), 69 VCC (power), 70 GND (power), 79 VCC (power), 80 GND (power), 81 TMS (in), 90 GND (power), 99 I2/CLK2 (in), 100 VCC (power), 101 GND (power), 102 I3/CLK3 (in), 111 GND (power), 120 TDO (out), 121 GND (power), 122 VCC (power), 131 GND (power), 132 VCC (power), 139 VCC (power), 140 GND (power), 141 GND (power), 142 VCC (power), 149 VCC (power), 150 GND (power), 159 VCC (power), 160 GND (power)

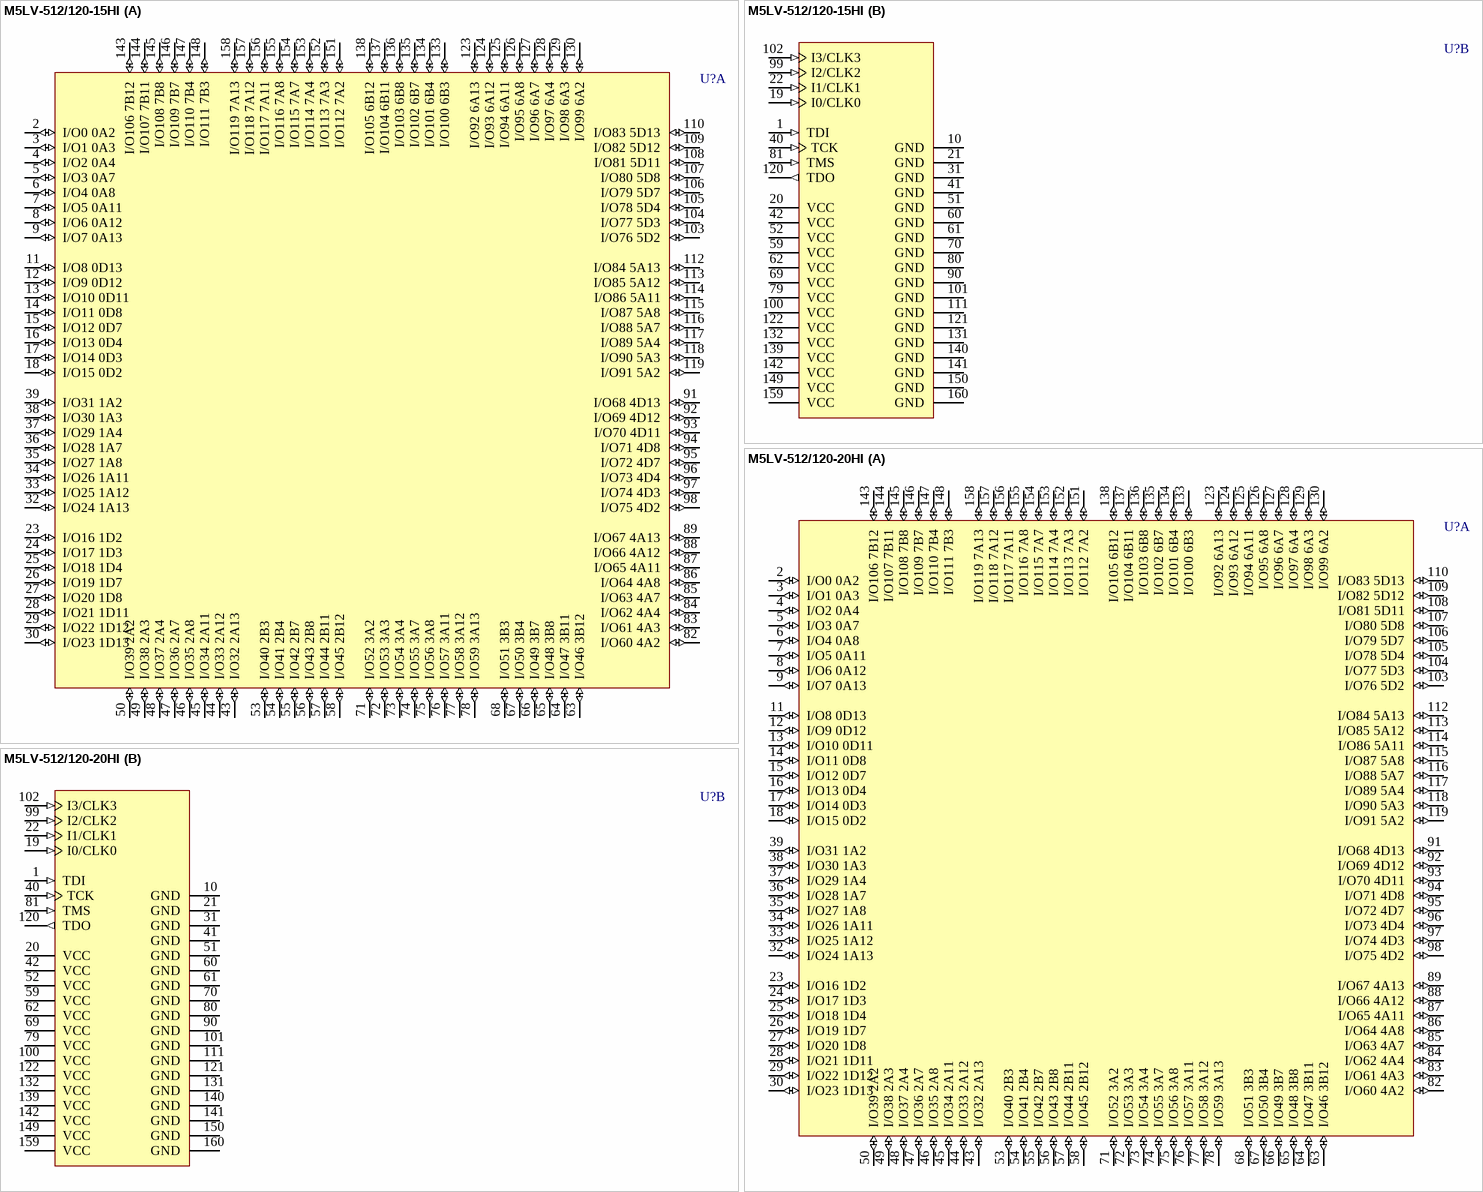
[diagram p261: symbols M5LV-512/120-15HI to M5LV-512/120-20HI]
